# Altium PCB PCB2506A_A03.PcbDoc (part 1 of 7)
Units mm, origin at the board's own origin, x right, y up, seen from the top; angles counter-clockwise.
Board outline 115 x 60 mm, 6 copper layers (Top Layer, Signal Layer 2, Signal Layer 3, Signal Layer 4, Signal Layer 5, Bottom Layer), stack 1.555 mm thick; 376 components, 290 nets, 1297 pads, 901 vias.
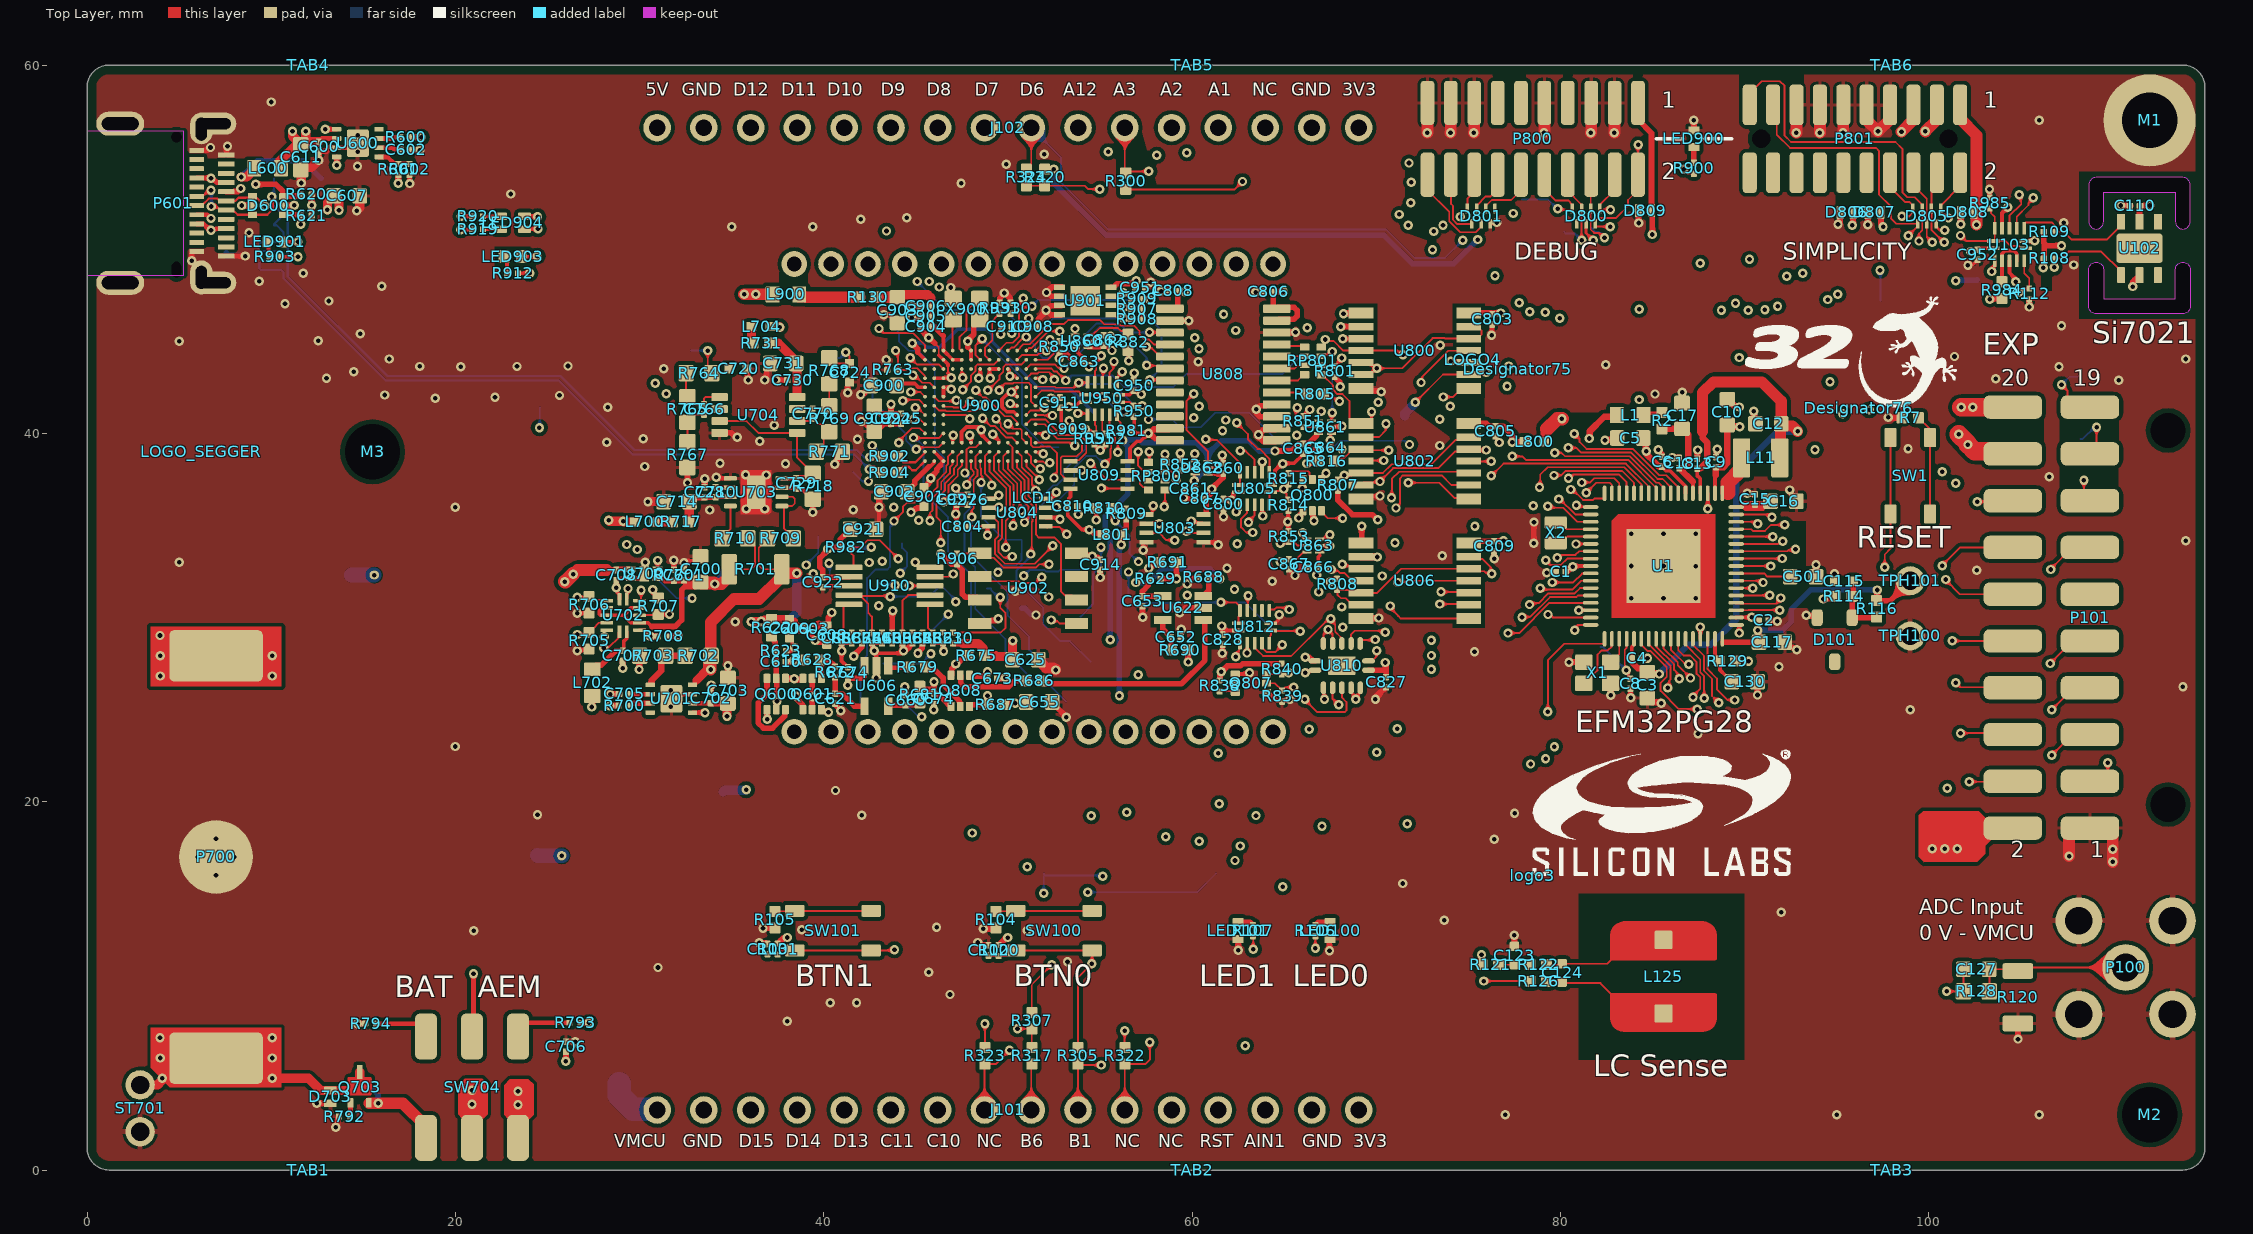
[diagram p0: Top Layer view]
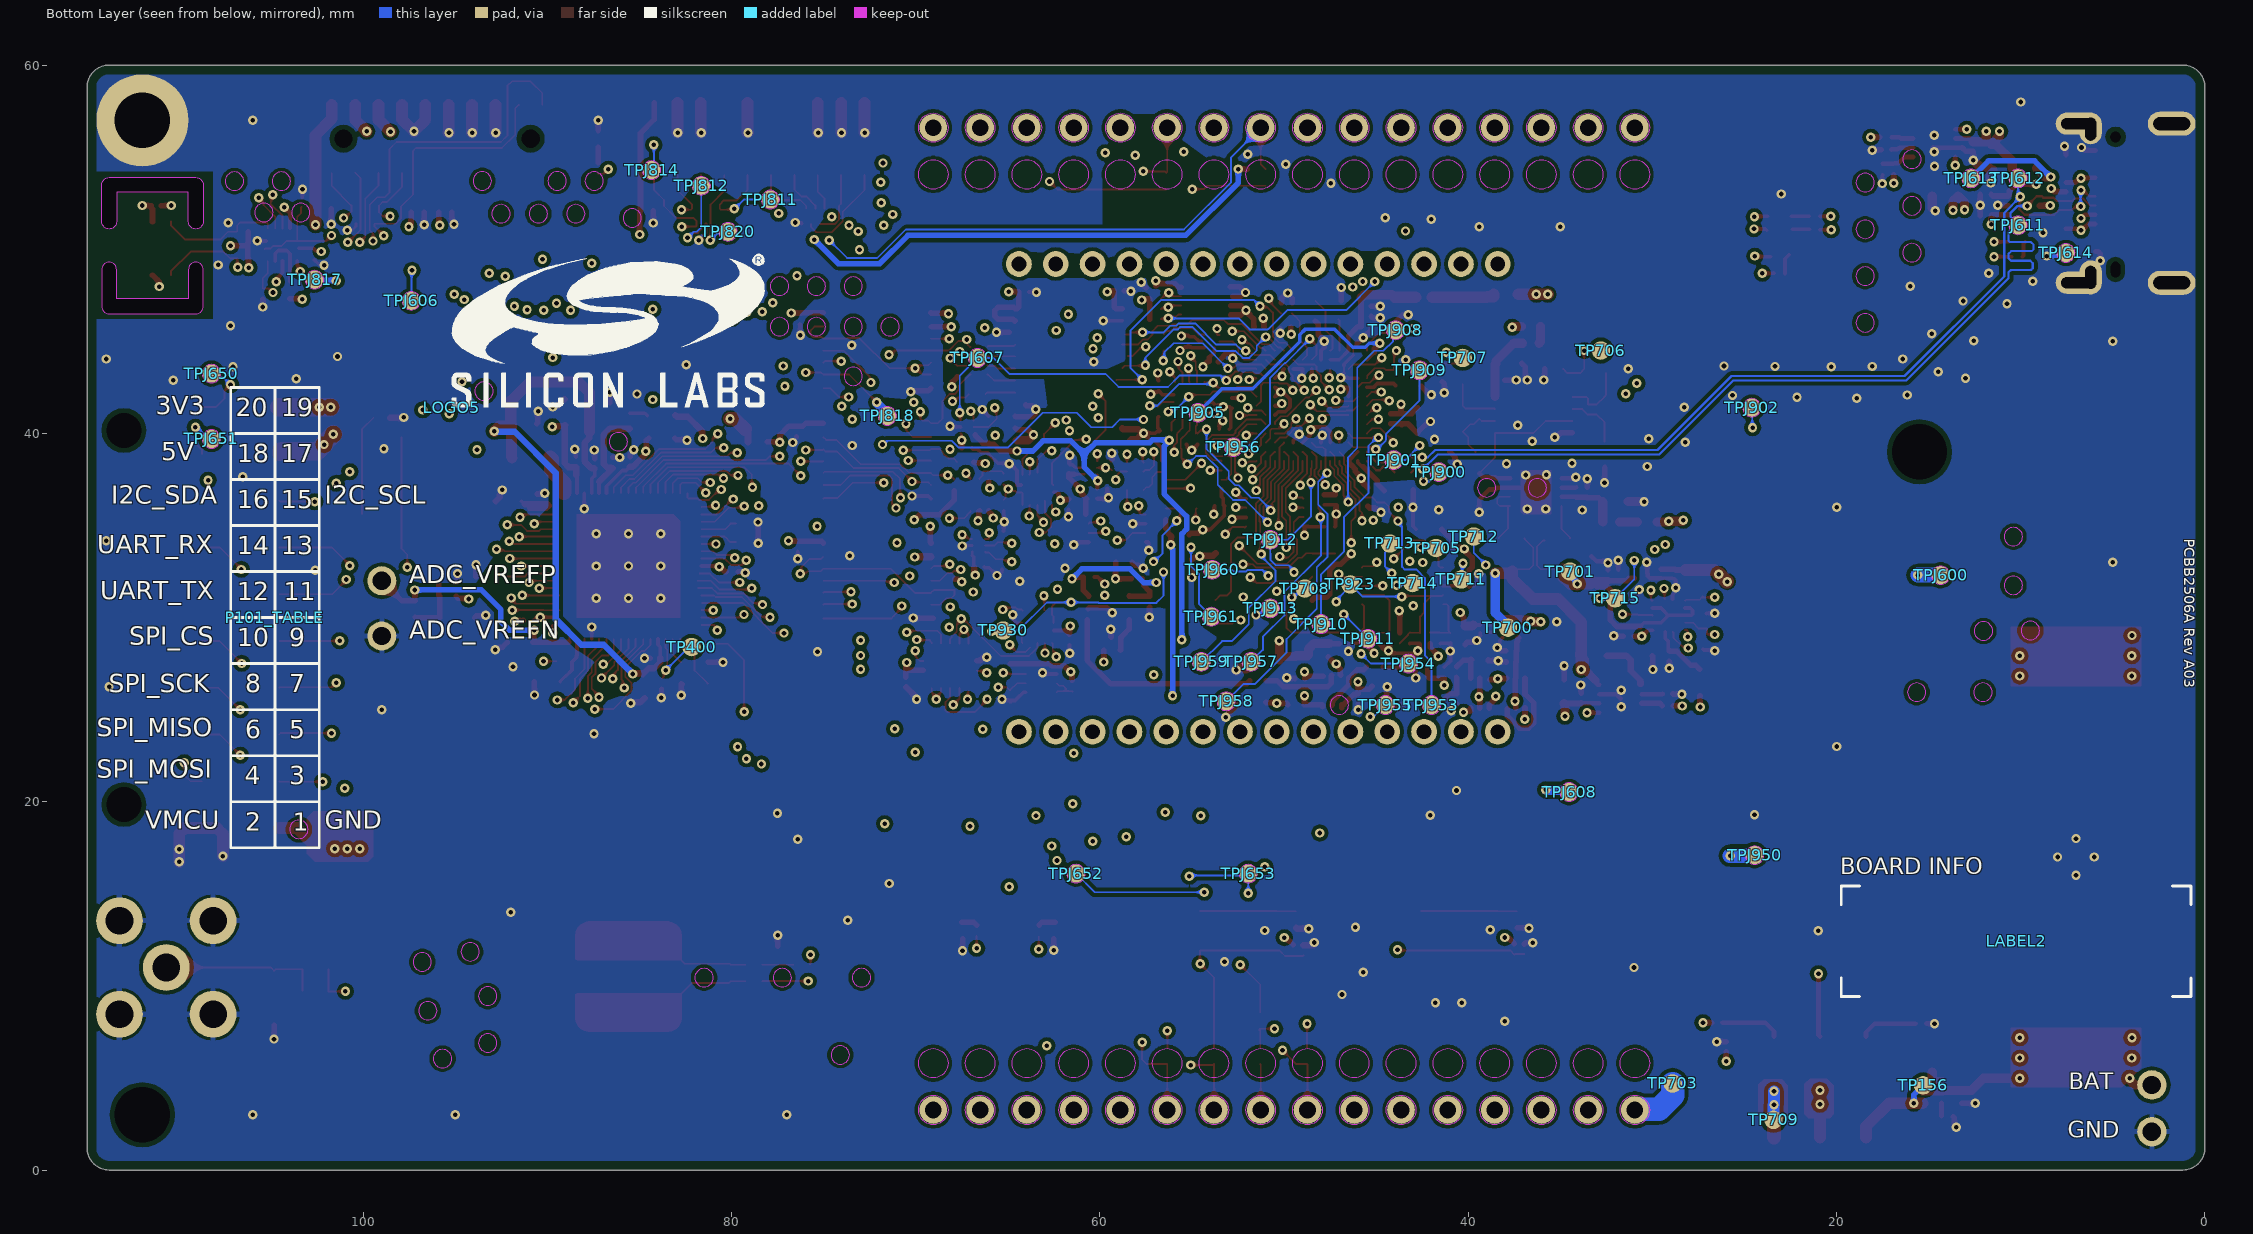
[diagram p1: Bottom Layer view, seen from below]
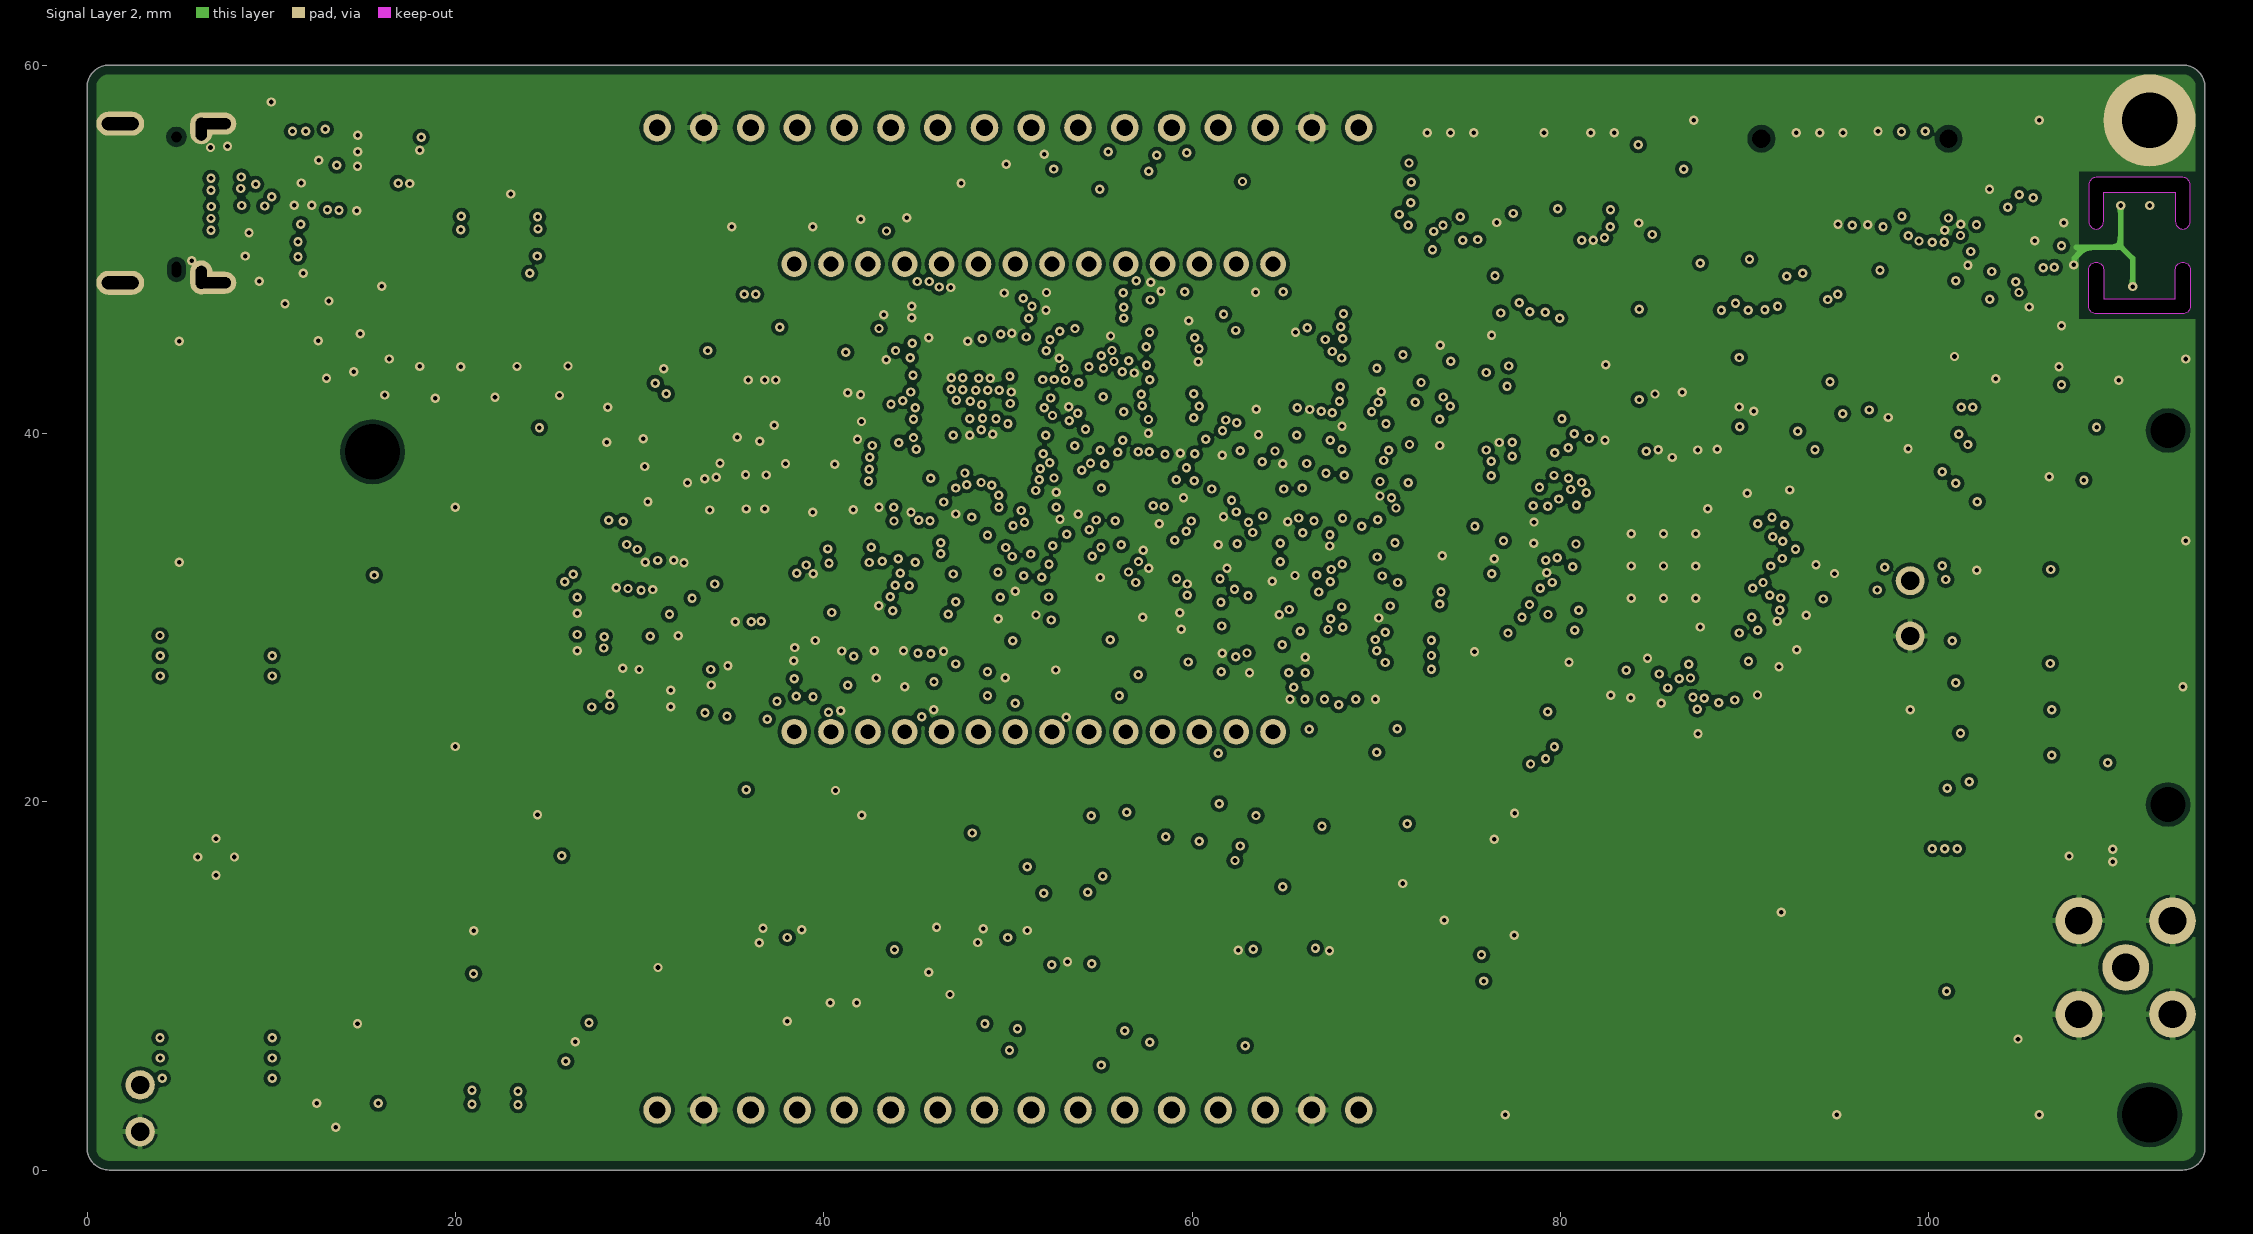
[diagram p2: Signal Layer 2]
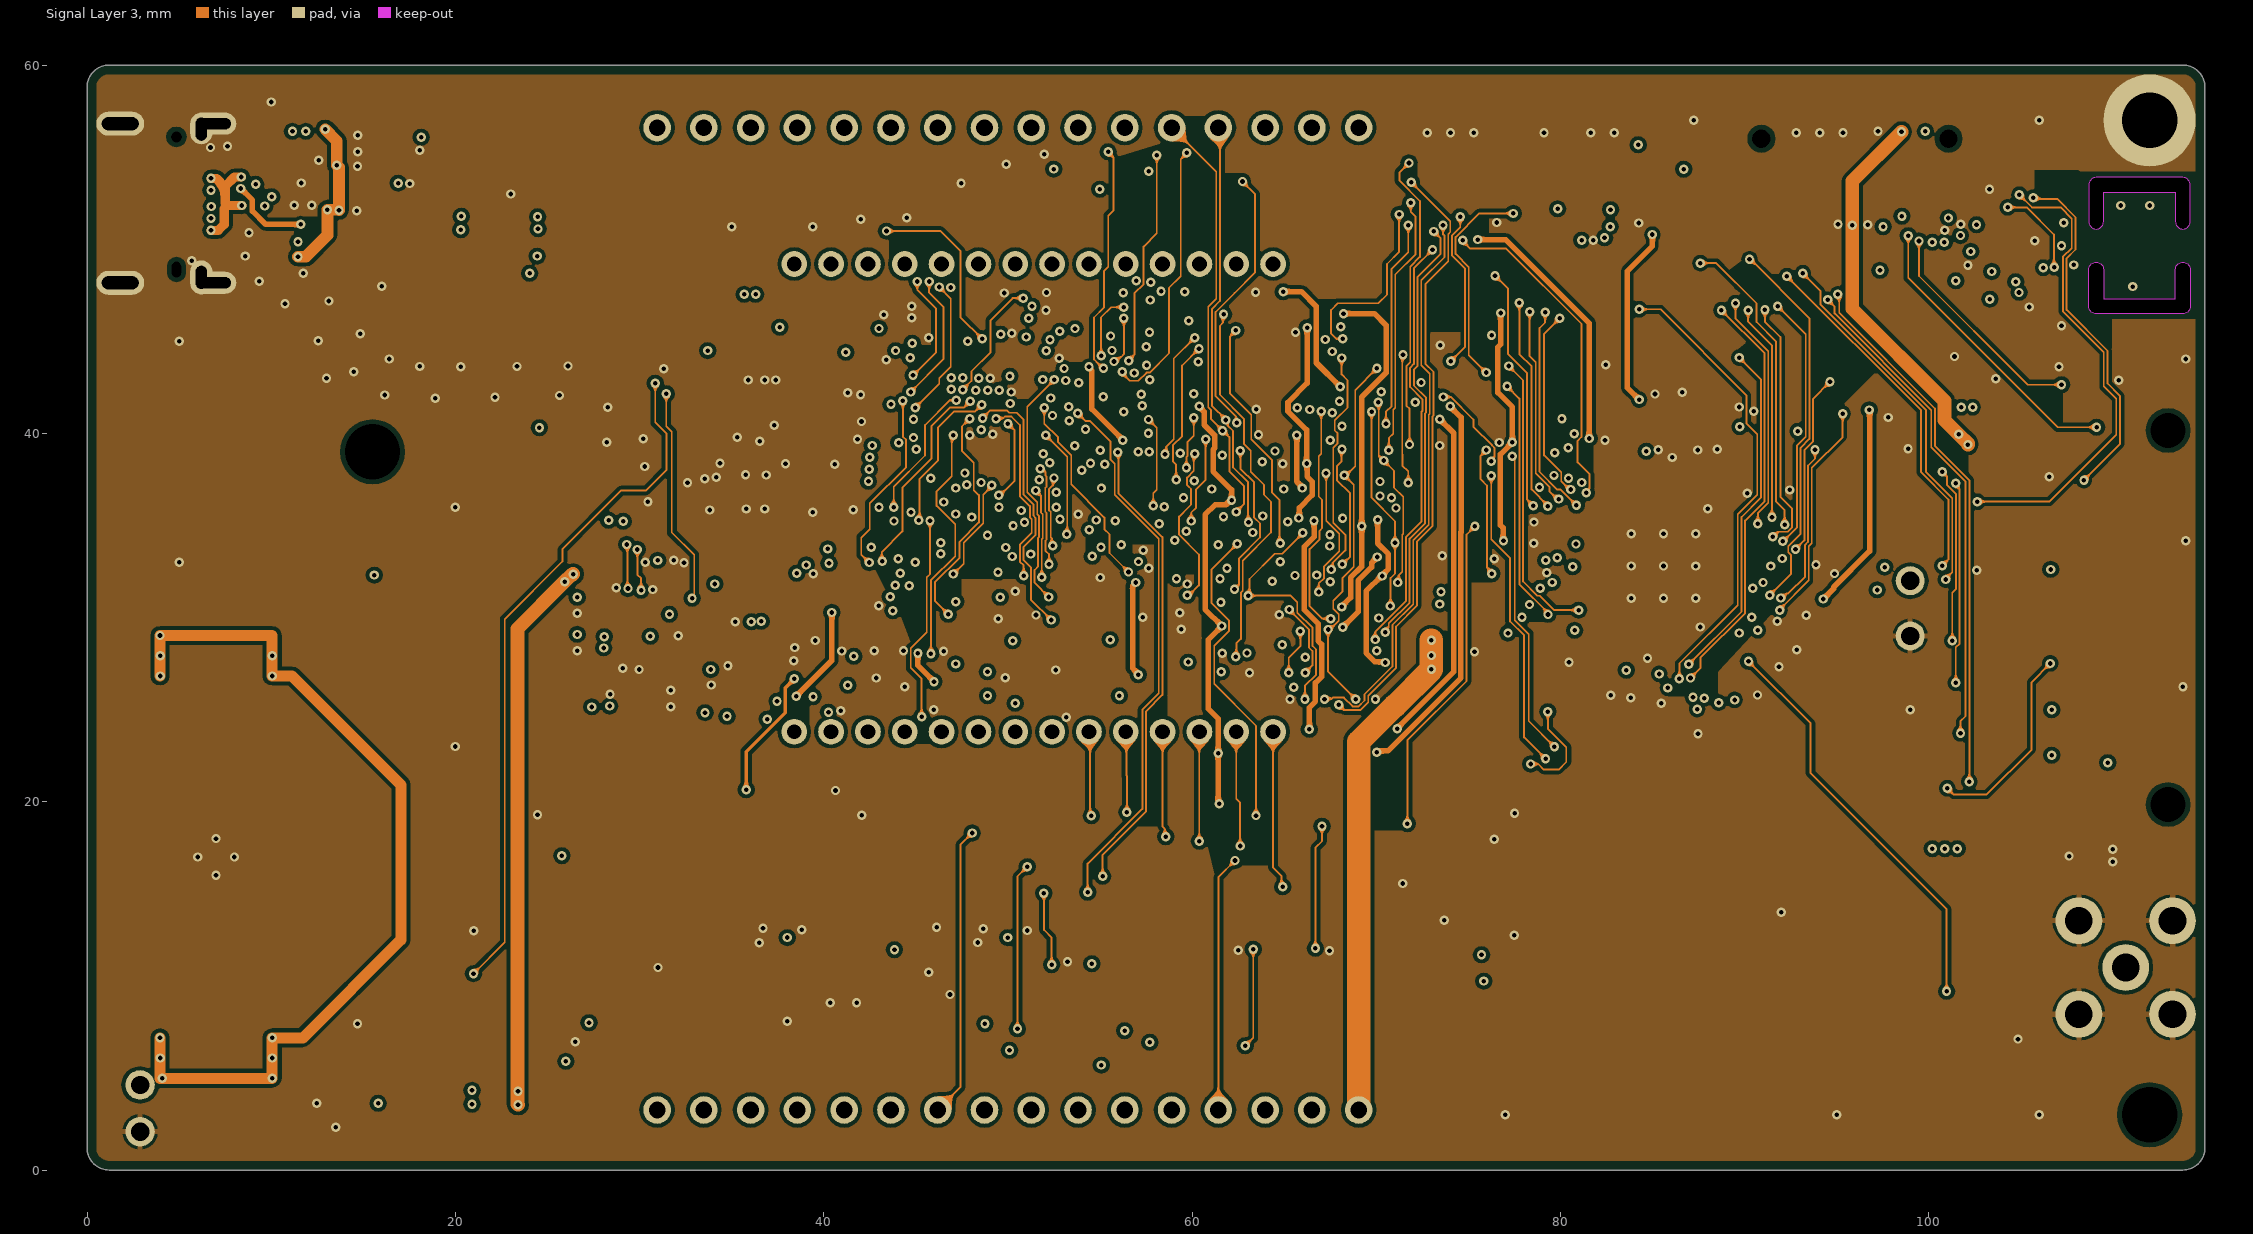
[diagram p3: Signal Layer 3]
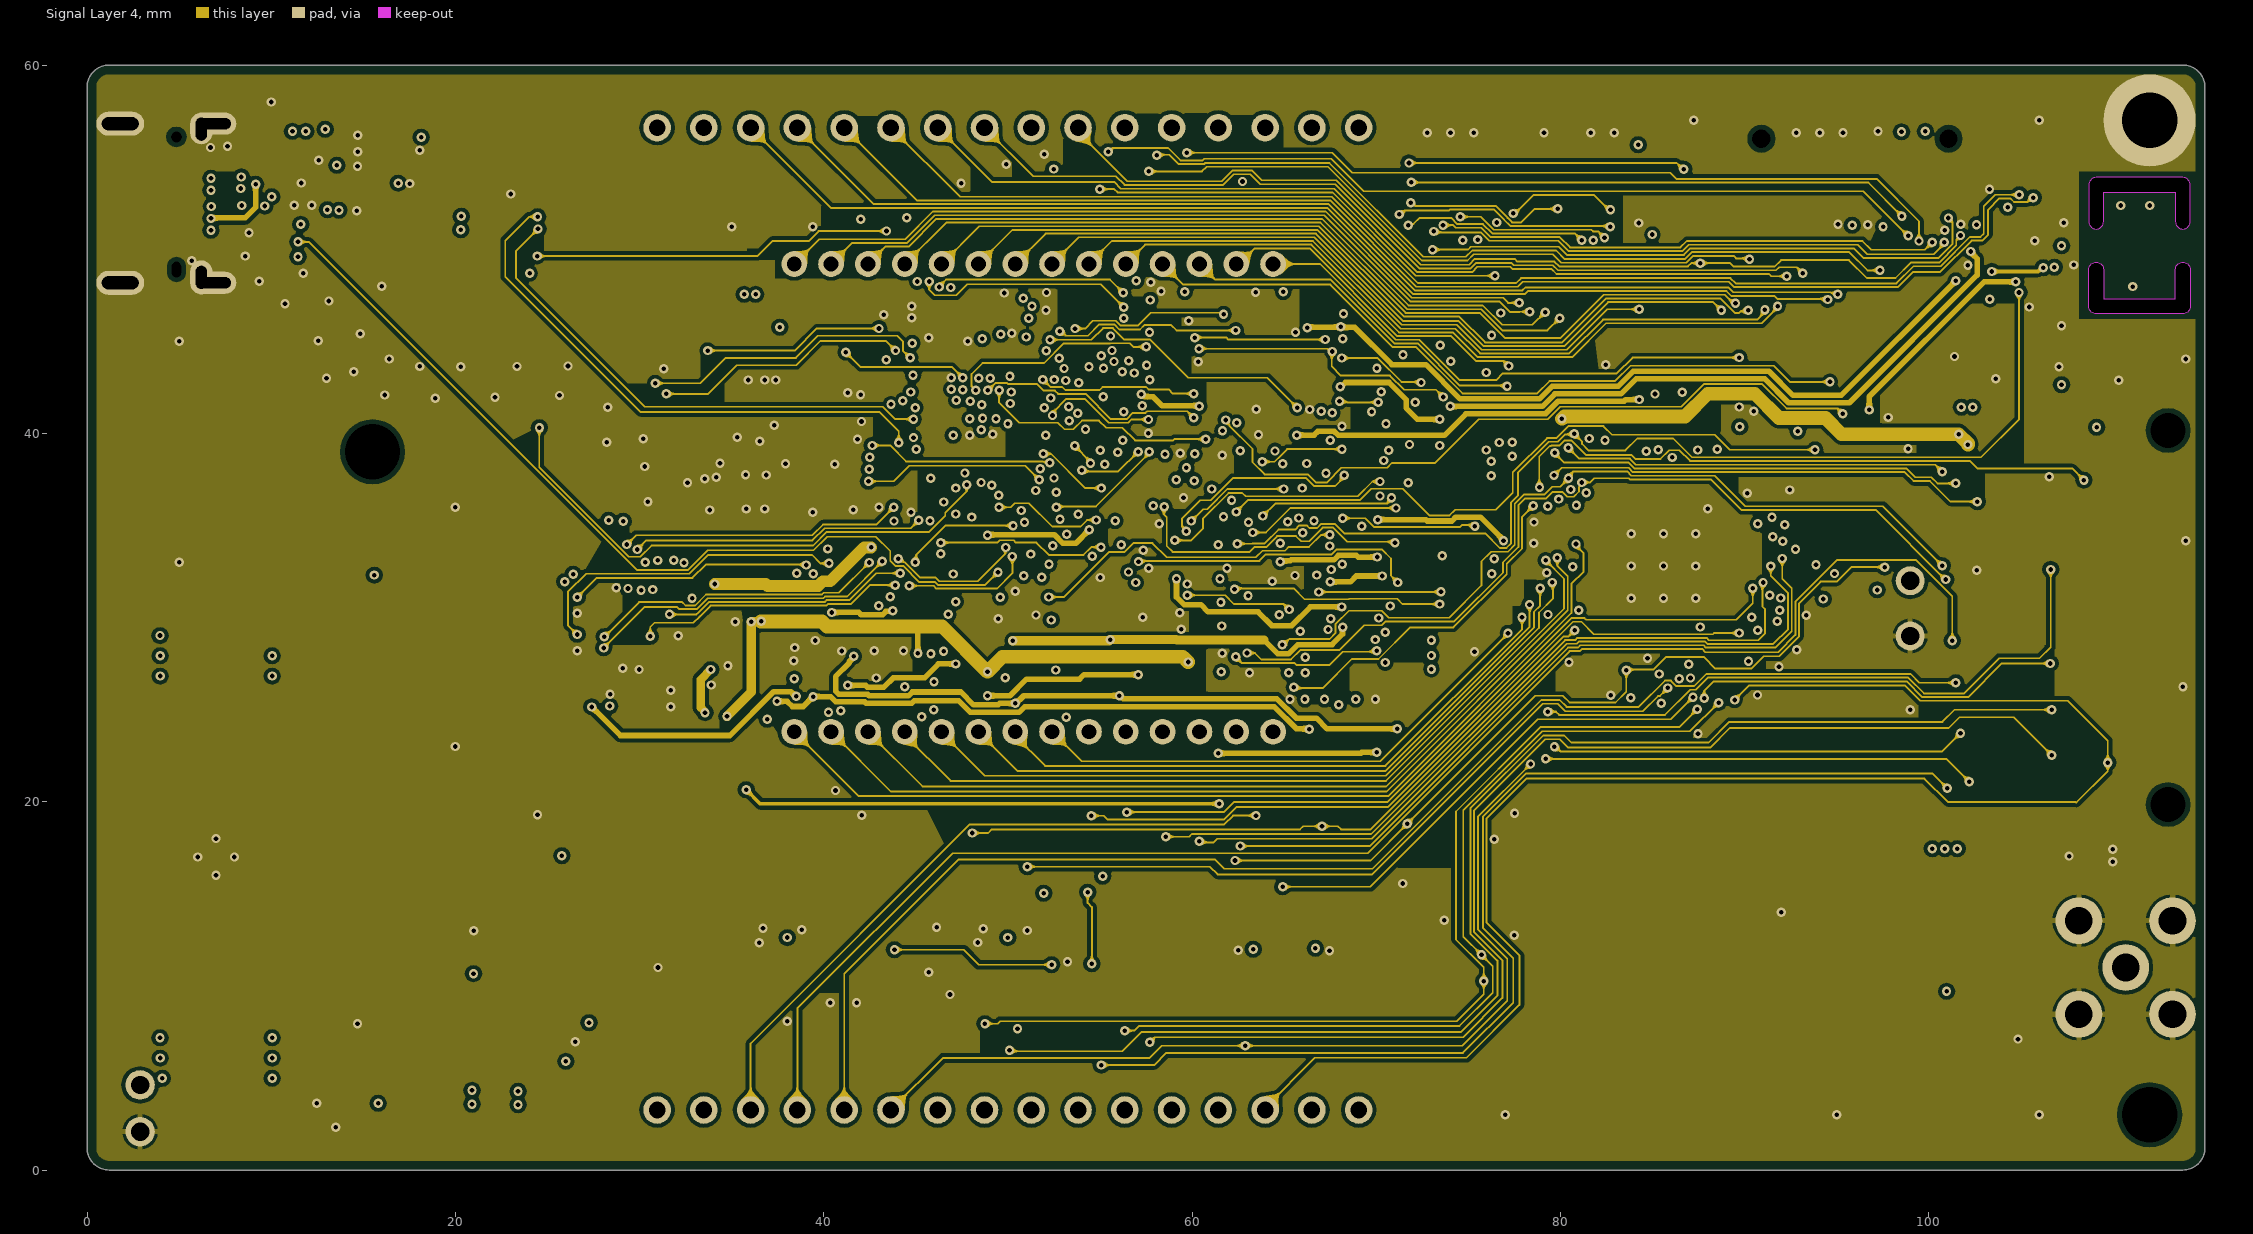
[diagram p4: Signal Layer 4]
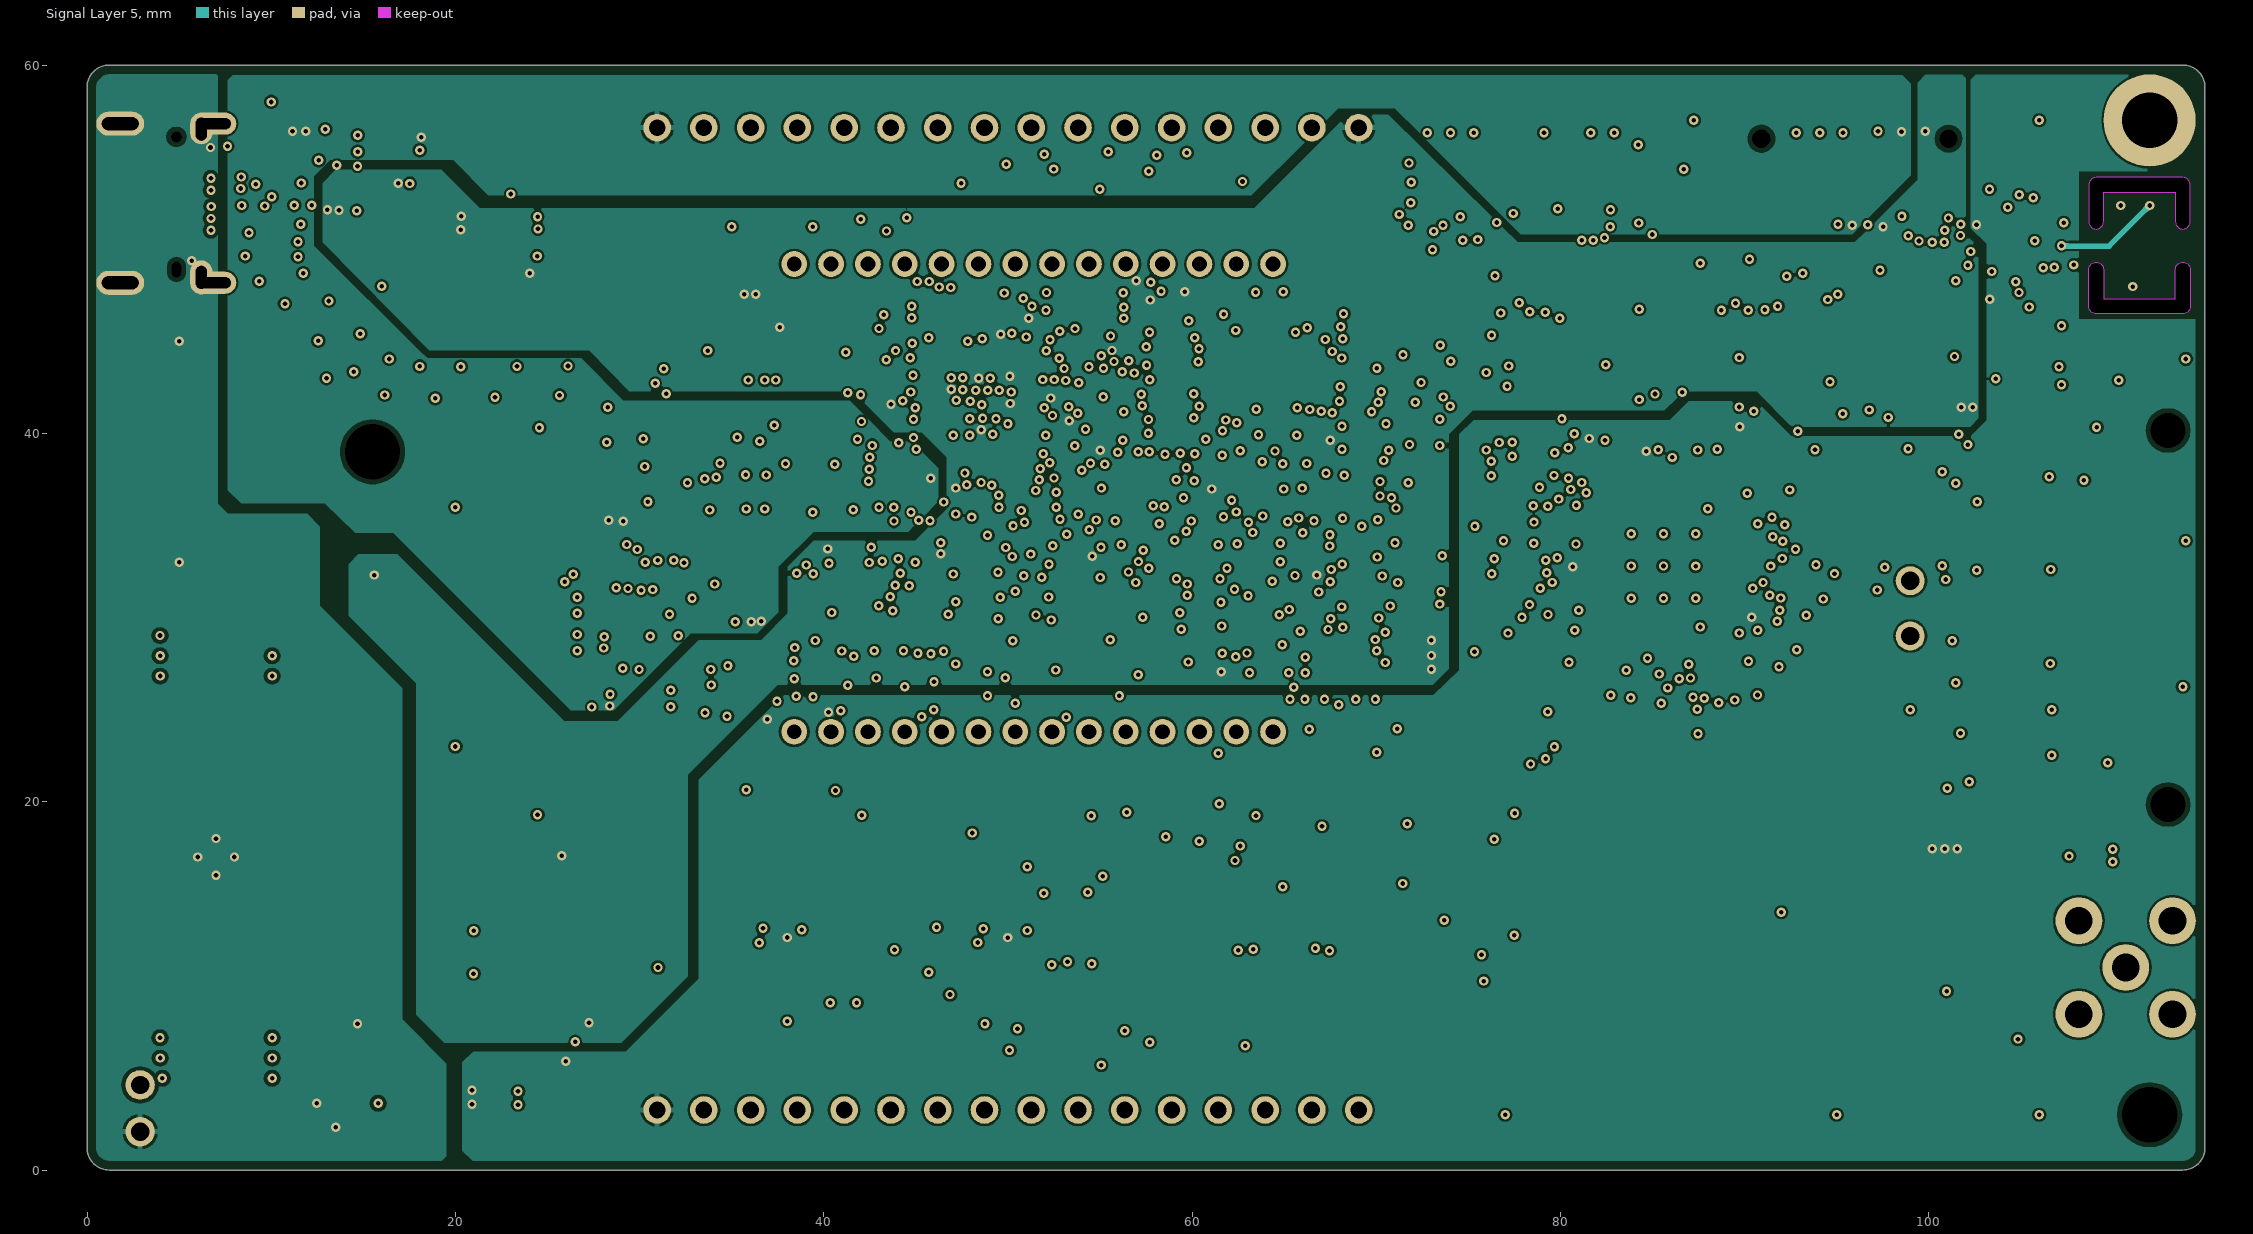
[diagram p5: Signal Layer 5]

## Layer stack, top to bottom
Top Solder: solder mask 0.03, Solder Resist, Dk 3.5
Top Layer: signal copper 0.035
Dielectric 1: prepreg 0.1, FR-4, Dk 4.2
Signal Layer 2: signal copper 0.035
Dielectric 2: core 0.46, Core-009, Dk 4.2
Signal Layer 3: signal copper 0.035
Dielectric 3: prepreg 0.225, PP-006, Dk 4.2
Signal Layer 4: signal copper 0.035
Dielectric 4: core 0.46, Core-009, Dk 4.2
Signal Layer 5: signal copper 0.035
Dielectric  5: prepreg 0.1, FR-4, Dk 4.2
Bottom Layer: signal copper 0.035
Bottom Solder: solder mask 0.03, Solder Resist, Dk 3.5

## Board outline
0,1.2 0,58.8 cw(c1.2,58.8) 1.2,60 113.8,60 cw(c113.8,58.8) 115,58.8 115,1.2 cw(c113.8,1.2) 113.8,0 1.2,0 cw(c1.2,1.2)
cut-out: 108.7,53.5 108.7,51.5 ccw(c109.1,51.5) 109.1,51.1 ccw(c109.1,51.5) 109.5,51.5 109.5,53.1 113.4,53.1 113.4,51.5 ccw(c113.8,51.5) 113.8,51.1 ccw(c113.8,51.5) 114.2,51.5 114.2,53.5 ccw(c113.8,53.5) 113.8,53.9 109.1,53.9 ccw(c109.1,53.5)
cut-out: 108.7,46.9 108.7,48.9 cw(c109.1,48.9) 109.1,49.3 cw(c109.1,48.9) 109.5,48.9 109.5,47.3 113.4,47.3 113.4,48.9 cw(c113.8,48.9) 113.8,49.3 cw(c113.8,48.9) 114.2,48.9 114.2,46.9 cw(c113.8,46.9) 113.8,46.5 109.1,46.5 cw(c109.1,46.9)

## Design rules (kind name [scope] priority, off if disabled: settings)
BoardOutlineClearance BoardOutlineClearance_IGNORE_USB [HasFootprint('FCI_10137065_USB-C_RCPT') and IsKeepOut] p1: gap=0.5 ignorepadtopadclearanceinfootprint=FALSE except(0: Region-OutlineEdge Region-CavityEdge Region-CutoutEdge Region-SplitBarrior Region-SplitContinuation; 0.26: Arc-CutoutEdge Track-CutoutEdge SMDPad-CutoutEdge THPad-CutoutEdge Via-CutoutEdge Fill-CutoutEdge Poly-CutoutEdge Text-CutoutEdge; 0.4: THPad-OutlineEdge)
BoardOutlineClearance [Not HasFootprint('TAB50.5_T1.6_W2.4') or not HasFootprint('FCI_10137065_USB-C_RCPT')] p2: gap=0.5 ignorepadtopadclearanceinfootprint=FALSE except(0.26: Arc-CutoutEdge Track-CutoutEdge SMDPad-CutoutEdge THPad-CutoutEdge Via-CutoutEdge Fill-CutoutEdge Poly-CutoutEdge Region-CutoutEdge Text-CutoutEdge; 0.4: THPad-OutlineEdge)
Clearance Clearance_NPL [(ObjectKind = 'Pad') And (Layer = 'MultiLayer') And (PadIsPlated = 'False')] p1: gap=0.25 ignorepadtopadclearanceinfootprint=FALSE
Clearance Clearance_Polygon_GND [InNet('GND') and InPolygon] p2: gap=0.2 ignorepadtopadclearanceinfootprint=FALSE
Clearance Clearance_Polygon_General [InPolygon] p3: gap=0.125 ignorepadtopadclearanceinfootprint=FALSE
Clearance Clearance_Via_Track [IsVia vs IsTrack] p4: gap=0.089 ignorepadtopadclearanceinfootprint=FALSE except(0: Arc-Hole Track-Hole SMDPad-Hole THPad-Hole Via-Hole Fill-Hole Poly-Hole Region-Hole Text-Hole)
Clearance [All] p5: gap=0.1 ignorepadtopadclearanceinfootprint=FALSE
ComponentClearance ComponentClearance_IGNORE [HasFootprint('TESTJIGG_PCB4002_M14') OR HasFootprint('TAB50.5_T1.6_W2.4') OR HasFootprint('TP_6.0X6.0_MILLOUT_5.0X5.0_TH') Or InComponent('M1')] p1: gap=0 collisioncheckmode=3 verticalgap=0 showdistances=FALSE
ComponentClearance [All] p2: gap=0.2 collisioncheckmode=3 verticalgap=0.254 showdistances=FALSE
DiffPairsRouting DiffPairsRouting_90OHM [InDifferentialPair('USB_90') or InDifferentialPair('USB_90_U900')] p1: maxlimit=0.254 minlimit=0.12 mostfreqgap=0.254 toplayer_maxgap=0.12 toplayer_prefgap=0.12 toplayer_minwidth=0.12 toplayer_maxwidth=0.12 toplayer_prefwidth=0.12 bottomlayer_maxgap=0.12 bottomlayer_prefgap=0.12 bottomlayer_minwidth=0.12 bottomlayer_maxwidth=0.12 bottomlayer_prefwidth=0.12 impedanceprofiledriven=TRUE impedanceprofileid={B4300C99-598D-4438-91CE-854F904B181D} impedanceprofilevalue=90.000000 maxuncoupledlength=50
HoleSize [All] p1: absolutevalues=TRUE maxlimit=10 minlimit=0.1 maxpercent=80.000 minpercent=20.000
HoleToHoleClearance HoleToHoleClearance_general [Not InComponent('P601')] p1: gap=0.254 allowstackedmicrovias=TRUE
MatchedLengths [All] p1: tolerance=0.1 checknetsindiffpair=TRUE checkdiffpairvsdiffpair=FALSE checkxsignals=FALSE checkothers=FALSE
MinimumSolderMaskSliver MinimumSolderMaskSliver_CK_DPDT_JS202011SCQN [All] p1: minsoldermaskwidth=0
MinimumSolderMaskSliver MinimumSolderMaskSliver_WELLSHOW_C02AN31_SMA_TH [HasFootprint('WELLSHOW_C02AN31_SMA_TH')] p2: minsoldermaskwidth=0
MinimumSolderMaskSliver MinimumSolderMaskSliver_DSBGA4_M040_0.8X0.8_TI_YFP [HasFootprint('DSBGA4_M040_0.8X0.8_TI_YFP')] p3: minsoldermaskwidth=0.09
MinimumSolderMaskSliver MinimumSolderMaskSliver_RES_MNR04-8 [HasFootprint('RES_MNR04-8')] p4: minsoldermaskwidth=0.05
MinimumSolderMaskSliver MinimumSolderMaskSliver_TSOP65P640X120-24L [HasFootprint('TSOP65P640X120-24L')] p5: minsoldermaskwidth=0.09
MinimumSolderMaskSliver MinimumSolderMaskSliver_QFN40P800X800X90_HS-69N [HasFootprint('QFN40P800X800X90_HS-69N')] p6: minsoldermaskwidth=0.04
MinimumSolderMaskSliver MinimumSolderMaskSliver_FCI_10137065_USB-C_RCPT [HasFootprint('FCI_10137065_USB-C_RCPT')] p7: minsoldermaskwidth=0
MinimumSolderMaskSliver MinimumSolderMaskSliver_SOT563Diodes [HasFootprint('SOT563_DIODES')] p8: minsoldermaskwidth=0.02
MinimumSolderMaskSliver MinimumSolderMaskSliver_EFM [InComponent('Designator75')] p9: minsoldermaskwidth=0
MinimumSolderMaskSliver MinimumSolderMaskSliver_C0201 [HasFootprint('C0201')] p10: minsoldermaskwidth=0.09
MinimumSolderMaskSliver MinimumSolderMaskSliver_IGNORE [InComponent('LOGO*') vs InComponent('LOGO*')] p11: minsoldermaskwidth=0
MinimumSolderMaskSliver [All] p12: minsoldermaskwidth=0.15
PolygonConnect PolygonConnect_P601 [InComponent('P601')] p1: connectstyle=Direct reliefconductorwidth=0.254 reliefentries=4 polygonreliefangle="90 Angle" airgapwidth=0.254
PolygonConnect [InComponent('J101') or InComponent('J102') vs InNet('GND') and not OnLayer('Signal Layer 2')] p2: connectstyle=NoConnect reliefconductorwidth=0.254 reliefentries=4 polygonreliefangle="90 Angle" airgapwidth=0.2
PolygonConnect PolygonConnect_Direct_Connect [InComponent('M1') or InComponent('J1') or InComponent('P700')] p3: connectstyle=Direct reliefconductorwidth=0.33 reliefentries=4 polygonreliefangle="90 Angle" airgapwidth=0.152
PolygonConnect PolygonConnect_general [All] p4: thpad.connectstyle=Relief thpad.reliefconductorwidth=0.3 thpad.reliefentries=4 thpad.polygonreliefangle="90 Angle" thpad.airgapwidth=0.15 smdpad.connectstyle=Relief smdpad.reliefconductorwidth=0.2 smdpad.reliefentries=4 smdpad.polygonreliefangle="90 Angle" smdpad.airgapwidth=0.15 via.connectstyle=Direct via.reliefconductorwidth=0.33 via.reliefentries=4 via.polygonreliefangle="90 Angle" via.airgapwidth=0.127
RoutingVias RoutingVias_Through [InDrillLayerPair('Top Layer - Bottom Layer')] p1: holewidth=0.25 width=0.508 viastyle="Through Hole" minholewidth=0.25 minwidth=0.508 maxholewidth=1 maxwidth=1.5 useviatemplates=TRUE viatemplateguid#1={5509B7CA-6DD0-459B-8D94-B04A75BB8EC3} viatemplatename#1=v51h25m0mx0(Tol8-8)
ShortCircuit ShortCircuit_General [All] p1: allowed=FALSE
SilkToSilkClearance [All] p1: silktosilkclearance=0.102
SilkToSolderMaskClearance [IsPad] p1: minsilkscreentomaskgap=0.102 clearancetoexposedcopper=TRUE
SolderMaskExpansion [All] p1: expansion=0.05 istentingtop=FALSE
UnRoutedNet [All] p1: checkbadconnections=TRUE
Width [All] p1: maxlimit=5.08 minlimit=0.1 preferedwidth=0.1 minimp=50.000000 maximp=50.000000 favimp=50.000000
21 further rules are at their usual default settings.

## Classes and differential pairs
net class USB_90: N16942491 N16942503 USB_DM USB_DP
differential pair USB_90_U900: +N16942503 -N16942491
differential pair USB_90: +USB_DP -USB_DM
differential pair ETH_RX: +"" -""
differential pair ETH_TX: +"" -""
differential pair USB: +"" -""

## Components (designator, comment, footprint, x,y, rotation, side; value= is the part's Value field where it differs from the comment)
C1 "100N" C0201#1 80.015,32.49 r180 top
C2 "100N" C0201#1 91.04,29.844 r0 top
C3 "4U7" C0603 84.725,26.329 r270 top
C4 "10N" C0201#2 84.147,27.804 r0 top
C5 "4U7" C0603 83.797,39.75 r180 top
C6 "100N" C0201#2 85.526,38.46 r90 top
C8 "100N" C0201#2 83.8,26.413 r270 top
C9 "100N" C0201#2 88.452,38.445 r90 top
C10 "10U" C0603 89.067,41.156 r90 top
C12 "4U7" C0603 91.295,40.525 r180 top
C13 "100N" C0201#2 87.433,38.354 r90 top
C15 "100N" C0201#2 90.567,36.418 r90 top
C16 "1U" C0603 92.118,36.316 r0 top
C17 "4U7" C0603 86.608,40.955 r90 top
C18 "10N" C0201#2 86.455,38.389 r90 top
C102 "1N" C0201#2 48.95,11.924 r90 top
C103 "1N" C0201#2 36.95,12 r90 top
C110 "100N" C0201#2 111.2,52.35 r180 top
C115 "1U" C0402 95.4,31.975 r180 top
C117 "10U" C0603 91.491,28.668 r0 top
C123 "100N" C0402 77.5,11.65 r90 top
C124 "330P" C0402 80.1,10.7 r270 top
C127 "4U7" C0603 102.589,10.9 r180 top
C130 "10N" C0603 90.009,26.515 r0 top
C501 "4U7" C0603 93.183,32.226 r180 top
C600 "100N" C0201#2 12.576,55.559 r270 top
C602 "33N" C0201#2 17.3,55.411 r0 top
C607 "10U" C0603 14.1,52.9 r0 top
C608 "1U" C0402 40.169,29.05 r270 top
C609 "1U" C0402 38.144,29.4 r270 top
C610 "1N" C0201#2 37.669,27.6 r0 top
C611 "10U" C0603 11.6,55 r270 top
C621 "100N" C0201#2 40.619,25.59 r270 top
C625 "10U" C0603 50.956,27.712 r0 top
C632 "10N" C0201#2 45.919,28.89 r270 top
C635 "10N" C0201#2 44.269,28.89 r270 top
C638 "10N" C0201#2 40.969,28.89 r270 top
C641 "10N" C0201#2 42.619,28.89 r270 top
C652 "100N" C0201#2 59.122,28.945 r0 top
C653 "100N" C0201#2 57.3,30.886 r270 top
C655 "10U" C0603 51.695,25.415 r0 top
C660 "100N" C0201#2 44.44,25.509 r90 top
C673 "100N" C0201#2 49.138,26.687 r0 top
C674 "100N" C0201#2 45.98,25.593 r270 top
C700 "10U" C0603 33.311,32.631 r90 top
C701 "100N" C0201#2 32.411,32.3 r90 top
C702 "100N" C0201#2 33.858,25.629 r90 top
C703 "10U" C0603 34.798,26.035 r90 top
C705 "33N" C0201#2 29.159,25.857 r180 top
C706 "100N" C0201#2 26,6.7 r90 top
C707 "100N" C0201#2 29.083,27.915 r270 top
C708 "100N" C0201#2 28.733,32.308 r270 top
C710 "100N" C0201#2 34.129,36.808 r90 top
C714 "10U" C0603 32.011,36.296 r180 top
C720 "1N" C0402 35.35,43.5 r0 top
C724 "1N" C0402 41.4,43.3 r270 top
C728 "100N" C0201#2 33.529,36.808 r90 top
C729 "2N2" C0201#2 38.504,37.283 r270 top
C730 "100N" C0201#2 38.3,42.9 r180 top
C731 "10U" C0603 37.8,43.8 r180 top
C766 "10P" C0201#2 33.5,41.3 r90 top
C770 "10P" C0201#2 39.4,41.075 r90 top
C800 "100N" C0201#2 61.707,36.161 r270 top
C803 "100N" C0201#2 76.301,46.191 r270 top
C804 "100N" C0201#2 47.516,34.936 r180 top
C805 "100N" C0201#2 76.479,40.116 r270 top
C806 "100N" C0201#2 64.147,47.703 r180 top
C807 "100N" C0201#2 60.42,36.445 r180 top
C808 "100N" C0201#2 58.95,47.75 r180 top
C809 "100N" C0201#2 76.402,33.863 r270 top
C810 "100N" C0201#2 53.5,36.055 r0 top
C827 "100N" C0201#2 70.535,26.493 r270 top
C828 "100N" C0201#2 61.67,28.805 r270 top
C860 "100N" C0201#2 61.695,38.1 r90 top
C861 "100N" C0201#2 59.884,36.994 r180 top
C862 "100N" C0201#2 55.2,45.05 r90 top
C863 "100N" C0201#2 53.85,43.9 r180 top
C864 "100N" C0201#2 67.225,39.214 r180 top
C865 "100N" C0201#2 66.036,39.17 r270 top
C866 "100N" C0201#2 66.582,32.745 r180 top
C867 "100N" C0201#2 65.256,32.89 r270 top
C900 "1U" C0603 43.25,42.6 r180 top
C901 "1U" C0402 45.45,36.55 r270 top
C902 "4U7" C0603 43.825,36.825 r180 top
C903 "10U" C0603 44,46.7 r270 top
C904 "10N" C0201#2 45.55,45.8 r180 top
C905 "10N" C0201#2 45.55,46.35 r180 top
C906 "10N" C0201#2 45.55,46.9 r180 top
C907 "4U7" C0603 42.75,40.8 r270 top
C908 "100N" C0201#2 51.35,45.8 r0 top
C909 "100N" C0201#2 53.25,40.225 r180 top
C910 "100N" C0201#2 49.95,45.8 r0 top
C911 "100N" C0201#2 52.825,41.675 r270 top
C914 "100N" C0201#2 55.013,32.864 r270 top
C921 "4U7" C0603 42.134,34.792 r0 top
C922 "100N" C0201#2 39.946,31.92 r270 top
C924 "100N" C0201#2 43.65,40.8 r270 top
C925 "100N" C0201#2 44.2,40.8 r270 top
C926 "100N" C0201#2 47.808,36.4 r270 top
C927 "100N" C0201#2 47.225,36.4 r270 top
C950 "10N" C0201#2 56.825,42.6 r90 top
C951 "100N" C0201#2 57.201,47.904 r0 top
C952 "100N" C0201#2 102.648,49.698 r270 top
D101 "ADR1581" SOT23 94.9,28.8 r270 top
D600 "DT1446-04" SOT563_DIODES 9.825,52.375 r180 top
D703 "ESD" X2-DFN1006-2 13.2,3.975 r270 top
D800 "PUSB3AB6_0" DFN2111-7_M050_1.2X2.1_NXP 81.4,51.8 r270 top
D801 "PUSB3AB6_0" DFN2111-7_M050_1.2X2.1_NXP 75.7,51.8 r270 top
D805 "PUSB3AB6_0" DFN2111-7_M050_1.2X2.1_NXP 99.9,51.8 r270 top
D806 "ESD" X2-DFN1006-2 95.55,52 r180 top
D807 "ESD" X2-DFN1006-2 97.05,52 r180 top
D808 "ESD" X2-DFN1006-2 102.1,52 r180 top
D809 "ESD" X2-DFN1006-2 84.6,52.1 r180 top
Designator75 "Comment" LOGO_EFM32_W18.0 77.7,43.5 r0 top
Designator76 "Comment" LOGO_GECKO_H6.0 96.2,41.4 r0 top
J101 "1X16 2.54MM" HDR_M254-1X16_NO_3D 30.95,3.262 r0 top locked
J102 "1X16 2.54MM" HDR_M254-1X16_NO_3D 30.95,56.602 r0 top locked
L1 "74279266" COIL_0603_L 83.797,40.998 r0 top
L11 "2U2" COIL_1008 90.882,38.673 r0 top
L125 "470uH" COIL_BOURNS_SDR0604 85.6,10.5 r270 top
L600 "742792662" COIL_0603_L 9.8,54.4 r0 top
L700 "742792796" COIL_0402 30.283,35.195 r0 top
L702 "74279266" COIL_0603_L 27.432,26.467 r90 top
L704 "742792796" COIL_0402 36.6,45.8 r180 top
L800 "742792796" COIL_0402 78.591,39.551 r180 top
L801 "742792796" COIL_0402 55.675,34.5 r180 top
L900 "74279266" COIL_0603_L 37.95,47.55 r0 top
LABEL2 "Comment" LABEL_4CORNERS_19.0X6.0 10.25,12.425 r180 bottom
LCD1 "CL010-1087-04" LCD_TRI-T_CL010-1087-03 51.4,36.5 r0 top locked
LED100 "Yellow" LED_0402_CAT2 67.5,13 r270 top
LED101 "Yellow" LED_0402_CAT2 62.5,13 r270 top
LED900 "YELLOW" LED_0402_CAT2 87.25,56 r90 top
LED901 "BLUE" LED_0402_CAT2 10.2,50.4 r0 top
LED903 "RED" DIOC1005X04N 23.101,49.6 r180 top
LED904 "LED_G_R" LED_AVAGO_HSMF-C165-4 23.101,51.439 r0 top
logo3 "Comment" LOGO_SILABS_W14.0_SILK 78.5,16 r0 top locked
LOGO4 "Comment" LOGO_EFM32_W18.0 75.232,44 r0 top locked
LOGO5 "Comment" LOGO_SILABS_W18.0 95.2,41.4 r180 bottom locked
LOGO_SEGGER "Comment" LOGO_SEGGER_10.0X5.0_SM 6.2,39 r0 top locked
M1 "HOLE_PTH_3MM" HOLE_3.0_5.0_PL 112,57 r0 top locked
M2 "Comment" HOLE_3.0_NPL 112,3 r0 top locked
M3 "Comment" HOLE_3.0_NPL 15.5,39 r90 top locked
P100 "SMA" WELLSHOW_C02AN31_SMA_TH 110.7,11 r0 top
P101 "HEADER_2X10_2.54MM_TH" WCON_1125B-1210_HOR_PEG-2X10 113,19.84 r90 top locked
P101_TABLE "Comment" LABEL_P101_PIN_TABLE_SL 104.8,30 r180 bottom
P601 "AMPHENOL_USB_TYPE-C" FCI_10137065_USB-C_RCPT 4.85,52.5 r270 top
P700 "CR2032" BAT_HOLD_MPD_BK-912_CR2032 7,17 r270 top locked
P800 "HEADER_DEBUG_ETM" WCON_3132_HDR_M127_SMD-2X10 78.5,56 r180 top locked
P801 "HEADER_2X10_1.27MM_SMD" HDR_SULLINS_M127_PEG-2X10 101.08,56 r180 top locked
Q600 "BSS84" SOT563_DIODES 37.419,25.85 r90 top
Q601 "DMN5L06VK" SOT563_DIODES 39.369,25.85 r90 top
Q703 "DMG3415" X2-DFN2015-3_DIODES 14.8,4.55 r90 top
Q800 "DMN5L06VK" SOT563_DIODES 66.533,36.65 r270 top
Q807 "DMN5L06VK" SOT563_DIODES 63.2,26.438 r180 top
Q808 "BSS84" SOT563_DIODES 47.415,26.019 r90 top
R2 "1R" R0402 85.522,40.698 r270 top
R7 "100R" R0402 99,40.85 r0 top
R100 "1M" R0201 49.5,11.924 r90 top
R101 "1M" R0201 37.5,12 r90 top
R104 "100R" R0402 49.35,13.6 r270 top
R105 "100R" R0402 37.35,13.6 r270 top
R106 "2K05" R0201 66.7,13 r270 top
R107 "2K05" R0201 63.3,13 r270 top
R108 "4K7" R0201 106.55,49.5 r0 top
R109 "4K7" R0201 106.55,50.95 r0 top
R112 "10M" R0201 105.461,47.574 r270 top
R114 "16K2" R0402 95.4,31.15 r180 top
R116 "205R" R0402 97.175,30.475 r270 top
R120 "49R9" R1206 104.845,9.382 r90 top
R121 "100R" R0402 76.2,11.15 r0 top
R122 "0R" R0402 78.8,11.15 r0 top
R126 "1K5" R0402 78.8,10.25 r0 top
R128 "549R" R0603 102.589,9.7 r180 top
R129 "14R" R0402 89.073,27.638 r180 top
R130 "1R" R0402 42.4,47.4 r0 top
R300 "0R" R0402 56.4,53.7 r270 top
R305 "0R" R0402 53.8,6.2 r90 top
R307 "0R" R0402 51.3,8.1 r90 top
R317 "0R" R0402 51.3,6.2 r270 top
R320 "10K" R0402 52,53.9 r90 top
R322 "0R" R0402 56.35,6.2 r270 top
R323 "0R" R0402 48.75,6.2 r270 top
R324 "1K" R0402 51,53.9 r270 top
R600 "10K" R0201 17.3,56.087 r0 top
R601 "180K" R0201 16.9,54.335 r270 top
R602 "110K" R0201 17.5,54.335 r90 top
R620 "5K1" R0201 11.9,52.975 r180 top
R621 "5K1" R0201 11.9,51.825 r180 top
R622 "47R" R0402 37.169,29.45 r90 top
R623 "10K" R0201 37.669,28.2 r180 top
R628 "1M" R0402 39.369,27.7 r180 top
R629 "1K" R0201 58,32.1 r0 top
R630 "4K7" R0201 47.019,28.89 r270 top
R631 "10K" R0201 46.469,28.89 r90 top
R633 "47K" R0201 45.369,28.89 r270 top
R634 "47K" R0201 44.819,28.89 r90 top
R636 "47K" R0201 42.069,28.89 r270 top
R637 "47K" R0201 41.519,28.89 r90 top
R639 "47K" R0201 43.719,28.89 r90 top
R640 "47K" R0201 43.169,28.89 r90 top
R672 "1K" R0201 40.619,27.04 r90 top
R674 "4K7" R0201 41.313,27 r90 top
R675 "3R3" R0402 48.278,27.931 r0 top
R679 "0R" R0402 45.079,27.315 r0 top
R681 "33R" R0402 45.216,25.82 r90 top
R686 "0R" R0402 51.418,26.559 r180 top
R687 "3R3" R0402 49.346,25.275 r0 top
R688 "4K7" R0201 60.604,32.2 r180 top
R690 "33R" R0402 59.335,28.228 r0 top
R691 "1M" R0402 58.692,33 r180 top
R700 "10K" R0201 29.159,25.222 r180 top
R701 "4R7" R1206 36.289,32.624 r180 top
R702 "180K" R0603 33.175,27.924 r0 top
R703 "110K" R0603 30.706,27.924 r0 top
R705 "267R" R0402 27.255,28.739 r90 top
R706 "10K2" R0402 27.255,30.7 r90 top
R707 "24K9" R0402 31.014,30.621 r270 top
R708 "1M" R0201 31.293,28.981 r180 top
R709 "1K8" R0603 37.643,34.3 r180 top
R710 "1K8" R0603 35.178,34.3 r0 top
R717 "10R" R0402 32.234,35.195 r0 top
R718 "12K" R0603 39.404,37.133 r90 top
R731 "1R" R0402 36.6,44.9 r180 top
R760 "330K" R0201 31.861,32.3 r270 top
R763 "100K" R0201 43.75,43.45 r0 top
R764 "90R9" R0603 33.225,43.275 r0 top
R765 "51K" R0603 32.6,41.3 r90 top
R767 "160R" R0603 32.6,38.85 r90 top
R768 "90R9" R0603 40.3,43.4 r90 top
R769 "51K" R0603 40.3,40.8 r90 top
R771 "51K" R0603 40.3,39 r180 top
R792 "1K" R0201 13.975,2.9 r0 top
R793 "10K" R0201 26.5,8 r0 top
R794 "510K" R0201 15.4,7.95 r180 top
R801 "47K" R0201 67.752,43.367 r270 top
R805 "33R" R0402 66.676,42.139 r0 top
R807 "4K7" R0201 67.92,37.194 r90 top
R808 "4K7" R0201 67.876,31.806 r270 top
R809 "100K" R0201 56.425,35.625 r270 top
R810 "33R" R0402 55.2,35.925 r0 top
R814 "100K" R0201 65.232,36.1 r90 top
R815 "1K" R0201 65.232,37.532 r270 top
R816 "100K" R0402 67.298,38.5 r180 top
R838 "100K" R0201 61.5,26.287 r90 top
R839 "10M" R0201 64.888,25.736 r90 top
R840 "100K" R0201 64.87,27.205 r90 top
R850 "100K" R0201 52.8,44.7 r90 top
R851 "100K" R0201 66.048,40.649 r270 top
R852 "100K" R0201 59.354,38.297 r270 top
R853 "100K" R0201 65.24,34.398 r270 top
R882 "220R" R0402 56.525,44.95 r270 top
R900 "2K05" R0201 87.25,54.4 r90 top
R902 "33R" R0402 43.55,38.75 r0 top
R903 "5K76" R0201 10.2,49.6 r180 top
R904 "33R" R0402 43.55,37.875 r0 top
R906 "10K" R0201 47.244,33.182 r270 top
R907 "4K7" R0201 57,46.75 r180 top
R908 "4K7" R0201 57,46.2 r180 top
R909 "10K" R0201 57,47.3 r180 top
R912 "2K37" R0201 23.101,48.7 r180 top
R919 "1K" R0201 21.201,51.089 r0 top
R920 "2K37" R0201 21.201,51.789 r0 top
R930 "1K" R0201 50.15,46.8 r90 top
R931 "1K" R0201 49.55,46.8 r90 top
R950 "100K" R0201 56.825,41.2 r270 top
R951 "100K" R0201 54.7,39.7 r90 top
R952 "100K" R0201 55.3,39.7 r90 top
R981 "100K" R0201 56.421,40.149 r0 top
R982 "10K" R0201 41.206,33.821 r0 top
R984 "0R" R0402 103.981,47.787 r90 top
R985 "10M" R0201 103.321,52.512 r90 top
RP800 "33R" RES_MNR04-8 58.082,37.678 r90 top
RP801 "33R" RES_MNR04-8 66.568,43.942 r90 top
ST701 "2X1 2.54MM" HDR_M254-1X2 2.875,2.08 r90 top locked
SW1 "PTS810" SW_CK_PTS810_SJM_250 99,37.7 r90 top
SW100 "PTS810" SW_CK_PTS810_SJM_250 52.5,13 r0 top
SW101 "PTS810" SW_CK_PTS810_SJM_250 40.5,13 r0 top
SW704 "DPDT_SW_SMD" CK_DPDT_JS202011SCQN 20.9,4.5 r180 top locked
TAB1 "Comment" TAB_V-CUT_L7.0_W2.4 12,0 r180 top
TAB2 "Comment" TAB_V-CUT_L7.0_W2.4 60,0 r180 top
TAB3 "Comment" TAB_V-CUT_L7.0_W2.4 98,0 r180 top
TAB4 "Comment" TAB_V-CUT_L7.0_W2.4 12,60 r0 top
TAB5 "Comment" TAB_V-CUT_L7.0_W2.4 60,60 r0 top
TAB6 "Comment" TAB_V-CUT_L7.0_W2.4 98,60 r0 top
TP156 "TP_SMD" TP_1.0_SMD 15.3,4.6 r180 bottom
TP400 "TP_SMD" TP_1.0_SMD 82.175,28.4 r180 bottom
TP700 "TP_SMD" TP_1.0_SMD 37.85,29.45 r90 bottom
TP701 "TP_SMD" TP_1.0_SMD 34.475,32.5 r90 bottom
TP703 "TP_SMD" TP_1.0_SMD 28.9,4.7 r180 bottom
TP705 "TP_SMD" TP_1.0_SMD 41.75,33.775 r180 bottom
TP706 "TP_SMD" TP_1.0_SMD 32.8,44.5 r90 bottom
TP707 "TP_SMD" TP_1.0_SMD 40.3,44.1 r90 bottom
TP708 "TP_SMD" TP_1.0_SMD 48.875,31.575 r90 bottom
TP709 "TP_SMD" TP_1.0_SMD 23.425,2.725 r90 bottom
TP711 "TP_SMD" TP_1.0_SMD 40.375,32.075 r90 bottom
TP712 "TP_SMD" TP_1.0_SMD 39.7,34.4 r90 bottom
TP713 "TP_SMD" TP_1.0_SMD 44.255,34.025 r90 bottom
TP714 "TP_SMD" TP_1.0_SMD 43.025,31.875 r90 bottom
TP715 "TP_SMD" TP_1.0_SMD 32.025,31.05 r180 bottom
TP923 "TP_SMD" TP_1.0_SMD 46.4,31.8 r90 bottom
TP930 "TP_SMD" TP_1.0_SMD 65.25,29.3 r180 bottom
TPH100 "PROTO_TH" PROTO_TH 99,29 r0 top
TPH101 "PROTO_TH" PROTO_TH 99,32 r0 top
TPJ600 "TP_SMD" TP_1.0_SMD 14.353,32.302 r90 bottom locked
TPJ606 "TP_SMD" TP_1.0_SMD 97.404,47.202 r90 bottom locked
TPJ607 "TP_SMD" TP_1.0_SMD 66.653,44.101 r90 bottom locked
TPJ608 "TP_SMD" TP_1.0_SMD 34.528,20.527 r90 bottom locked
TPJ611 "TP_SMD" TP_1.0_SMD 10.15,51.3 r180 bottom locked
TPJ612 "TP_SMD" TP_1.0_SMD 10.15,53.85 r180 bottom locked
TPJ613 "TP_SMD" TP_1.0_SMD 12.7,53.85 r180 bottom locked
TPJ614 "TP_SMD" TP_1.0_SMD 7.55,49.8 r180 bottom locked
TPJ650 "TP_SMD" TP_1.0_SMD 108.25,43.248 r90 bottom locked
TPJ651 "TP_SMD" TP_1.0_SMD 108.25,39.7 r90 bottom locked
TPJ652 "TP_SMD" TP_1.0_SMD 61.303,16.102 r90 bottom locked
TPJ653 "TP_SMD" TP_1.0_SMD 51.953,16.102 r90 bottom locked
TPJ811 "TP_SMD" TP_1.0_SMD 77.9,52.7 r180 bottom locked
TPJ812 "TP_SMD" TP_1.0_SMD 81.65,53.45 r180 bottom locked
TPJ814 "TP_SMD" TP_1.0_SMD 84.35,54.3 r180 bottom locked
TPJ817 "TP_SMD" TP_1.0_SMD 102.65,48.35 r180 bottom locked
TPJ818 "TP_SMD" TP_1.0_SMD 71.55,40.95 r180 bottom locked
TPJ820 "TP_SMD" TP_1.0_SMD 80.2,50.95 r180 bottom locked
TPJ900 "TP_SMD" TP_1.0_SMD 41.602,37.9 r90 bottom locked
TPJ901 "TP_SMD" TP_1.0_SMD 44.053,38.55 r90 bottom locked
TPJ902 "TP_SMD" TP_1.0_SMD 24.6,41.4 r180 bottom locked
TPJ905 "TP_SMD" TP_1.0_SMD 54.678,41.126 r90 bottom
TPJ908 "TP_SMD" TP_1.0_SMD 43.952,45.601 r90 bottom locked
TPJ909 "TP_SMD" TP_1.0_SMD 42.651,43.427 r90 bottom locked
TPJ910 "TP_SMD" TP_1.0_SMD 48.003,29.65 r90 bottom locked
TPJ911 "TP_SMD" TP_1.0_SMD 45.453,28.85 r90 bottom locked
TPJ912 "TP_SMD" TP_1.0_SMD 50.751,34.225 r90 bottom locked
TPJ913 "TP_SMD" TP_1.0_SMD 50.751,30.501 r90 bottom locked
TPJ950 "TP_SMD" TP_1.0_SMD 24.452,17.1 r90 bottom locked
TPJ953 "TP_SMD" TP_1.0_SMD 42.001,25.251 r90 bottom locked
TPJ954 "TP_SMD" TP_1.0_SMD 43.253,27.501 r90 bottom locked
TPJ955 "TP_SMD" TP_1.0_SMD 44.503,25.251 r90 bottom locked
TPJ956 "TP_SMD" TP_1.0_SMD 52.753,39.251 r90 bottom locked
TPJ957 "TP_SMD" TP_1.0_SMD 51.799,27.599 r180 bottom locked
TPJ958 "TP_SMD" TP_1.0_SMD 53.15,25.45 r180 bottom locked
TPJ959 "TP_SMD" TP_1.0_SMD 54.499,27.599 r90 bottom locked
TPJ960 "TP_SMD" TP_1.0_SMD 53.899,32.598 r90 bottom locked
TPJ961 "TP_SMD" TP_1.0_SMD 53.95,30.05 r180 bottom locked
U1 "EFM32PG28B310F1024IM68-A" QFN40P800X800X90_HS-69N 85.6,32.8 r0 top
U102 "Si7021-A20" DFN6_M100_3.0X3.0_EP_SI7021 111.45,50.05 r90 top
U103 "TS3A4751" QFN14_M040_2.0X2.0_TI_RUC 104.388,50.251 r90 top
U600 "LP3982ILD-ADJ" LLP8_MA65_W3.0 14.7,55.763 r0 top
U603 "TLV70536" DSBGA4_M040_0.8X0.8_TI_YFP 39.15,29.4 r180 top
U606 "MCP6001T" SOT65P210X110-5N 42.861,26.292 r270 top
U622 "MCP6001T" SOT65P210X110-5N 59.5,30.521 r180 top
U700 "SIP32431" TDFN4_M050_1.6X1.2_EP_VISH 30.258,32.384 r0 top
U701 "LP3982ILD-ADJ" LLP8_MA65_W3.0 31.728,25.592 r180 top
U702 "TS3A4751" QFN14_M040_2.0X2.0_TI_RUC 29.111,30.119 r180 top
U703 "LTC6102CDD" DFN8_M050_3.0X3.0_EP_LT_DD 36.329,36.808 r180 top
U704 "AD8656" MSOP8_M065_W3.0 36.45,41 r0 top
U800 "74LVC4066" TSOP65P640X110-14L_A1 72.1,44.5 r0 top
U802 "74LVC4066" TSOP65P640X110-14L_A1 72.1,38.5 r0 top
U803 "SN74LVC2G125DCUR" TSSOP50P310X90-8L 59.071,34.849 r0 top
U804 "SN74LVC2G125DCUR" TSSOP50P310X90-8L 50.503,35.704 r180 top
U805 "TS3A4751" QFN14_M040_2.0X2.0_TI_RUC 63.4,37 r90 top
U806 "74LVC4066" TSOP65P640X110-14L_A1 72.1,32 r0 top
U808 "74LVC8T245" TSOP65P640X120-24L 61.7,43.2 r0 top
U809 "SN74LVC2G125DCUR" TSSOP50P310X90-8L 54.948,37.735 r180 top
U810 "74LVC4066" DHVQFN14_M050_2.5X3_EP_NXP 68.135,27.393 r270 top
U812 "TS3A4751" QFN14_M040_2.0X2.0_TI_RUC 63.4,29.5 r90 top
U860 "74LVC1T45" SON35P100X35-6L 54,45 r90 top
U861 "74LVC1T45" SON35P100X35-6L 67.223,40.343 r90 top
U862 "74LVC1T45" SON35P100X35-6L 60.523,38.135 r90 top
U863 "74LVC1T45" SON35P100X35-6L 66.586,33.913 r90 top
U900 "EFM32GG12B410F1024GL120-A" BGA120_M050_7.0X7.0_EFM32GGR 48.5,41.5 r180 top
U901 "M24C02" DFN50P300X60_HS-9N 54.2,47.2 r0 top
U902 "MX25R8035F" SOP127P600X175-8L 51.097,31.589 r0 top
U910 "ADC084S021" VSSOP10_M050_W3.0_TI_DGS 43.574,31.72 r0 top
U950 "TS3A4751" QFN14_M040_2.0X2.0_TI_RUC 55.125,41.9 r270 top
X1 "39 MHz" XTAL200X160X50 82,27 r0 top
X2 "32.768 kHz" XTAL160X100X50 79.751,34.6 r90 top
X900 "48 MHz" XTAL200X160X50 47.75,46.75 r0 top
? "Comment" LOGO_GECKO_H6.0 95,41.35 r0 top

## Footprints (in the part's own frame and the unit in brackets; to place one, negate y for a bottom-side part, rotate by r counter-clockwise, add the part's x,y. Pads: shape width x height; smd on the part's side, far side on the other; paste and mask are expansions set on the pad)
BAT_HOLD_MPD_BK-912_CR2032 [mil] "MPD Battery Holder BK-912 (for CR2032)"
  rrect20% 110x200 smd: 1(-430,0) 1(430,0)
  round 157.48 smd paste-295.67 mask-82.68: 2(0,0)
  body extent -450,-394 450,393, height 171
BGA120_M050_7.0X7.0_EFM32GGR [mm] "BGA, 120 Leads, Body 7.0x7.0mmx1,30mm, Pitch 0.50mm (191111)"
  round 0.2 smd mask+0.04: A1(-3,3) A2(-2.5,3) A3(-2,3) A4(-1.5,3) A5(-1,3) A6(-0.5,3) A7(0,3) A8(0.5,3) A9(1,3) A10(1.5,3) A11(2,3) A12(2.5,3) A13(3,3) B1(-3,2.5) B2(-2.5,2.5) B3(-2,2.5) B4(-1.5,2.5) B5(-1,2.5) B6(-0.5,2.5) B7(0,2.5) B8(0.5,2.5) B9(1,2.5) B10(1.5,2.5) B11(2,2.5) B12(2.5,2.5) B13(3,2.5) C1(-3,2) C2(-2.5,2) C3(-2,2) C4(-1.5,2) C5(-1,2) C6(-0.5,2) C7(0,2) C8(0.5,2) C9(1,2) C10(1.5,2) C11(2,2) C12(2.5,2) C13(3,2) D1(-3,1.5) D2(-2.5,1.5) D3(-2,1.5) D11(2,1.5) D12(2.5,1.5) D13(3,1.5) E1(-3,1) E2(-2.5,1) E3(-2,1) E11(2,1) E12(2.5,1) E13(3,1) F1(-3,0.5) F2(-2.5,0.5) F3(-2,0.5) F11(2,0.5) F12(2.5,0.5) F13(3,0.5) G1(-3,0) G2(-2.5,0) G3(-2,0) G11(2,0) G12(2.5,0) G13(3,0) H1(-3,-0.5) H2(-2.5,-0.5) H3(-2,-0.5) H11(2,-0.5) H12(2.5,-0.5) H13(3,-0.5) J1(-3,-1) J2(-2.5,-1) J3(-2,-1) J11(2,-1) J12(2.5,-1) J13(3,-1) K1(-3,-1.5) K2(-2.5,-1.5) K3(-2,-1.5) K11(2,-1.5) K12(2.5,-1.5) K13(3,-1.5) L1(-3,-2) L2(-2.5,-2) L3(-2,-2) L4(-1.5,-2) L5(-1,-2) L6(-0.5,-2) L7(0,-2) L8(0.5,-2) L9(1,-2) L10(1.5,-2) L11(2,-2) L12(2.5,-2) L13(3,-2) M1(-3,-2.5) M2(-2.5,-2.5) M3(-2,-2.5) M4(-1.5,-2.5) M5(-1,-2.5) M6(-0.5,-2.5) M7(0,-2.5) M8(0.5,-2.5) M9(1,-2.5) M10(1.5,-2.5) M11(2,-2.5) M12(2.5,-2.5) M13(3,-2.5) N1(-3,-3) N2(-2.5,-3) N3(-2,-3) N4(-1.5,-3) N5(-1,-3) N6(-0.5,-3) N7(0,-3) N8(0.5,-3) N9(1,-3) N10(1.5,-3) N11(2,-3) N12(2.5,-3) N13(3,-3)
  body extent -3.5,-3.5 3.5,3.5, height 1.3
C0201#1 [mm] "Capacitor, 9291, HiDens (170502)"
  rrect25% 0.36x0.32 smd paste-0.015: 1(-0.275,0) 2(0.275,0)
  Top Layer pour cut-out: -0.075,-0.2 -0.075,0.2 0.075,0.2 0.075,-0.2
  body extent -0.32,-0.13 0.32,0.13, height 0.3
C0201#2 [mm] "Capacitor, 9291, HiDens (170502)"
  rrect25% 0.36x0.32 smd paste-0.015 mask+0.05: 1(-0.275,0) 2(0.275,0)
  Top Layer pour cut-out: -0.075,-0.2 -0.075,0.2 0.075,0.2 0.075,-0.2
  body extent -0.32,-0.13 0.32,0.13, height 0.3
C0402 [mm] "Chip Capacitor, 2-Leads, Body 1.0x0.5mm, IPC High Density (190308)"
  rrect20% 0.5x0.5 smd mask+0.051: 1(-0.5,0) 2(0.5,0)
  Top Layer pour cut-out: -0.225,-0.3 -0.225,0.3 0.225,0.3 0.225,-0.3
  body extent -0.5,-0.25 0.5,0.25, height 0.6
C0603 [mm] "Capacitor, 0603, HiDens (190130)"
  rrect25% 0.8x0.85 smd: 1(-0.7,0) 2(0.7,0)
  Top Layer pour cut-out: -0.275,-0.55 -0.275,0.55 0.275,0.55 0.275,-0.55
  body extent -0.88,-0.48 0.87,0.48, height 0.95
CK_DPDT_JS202011SCQN [mm] "Switch, C & K DPDT JS202011SCQN (190314)"
  rrect50% 1.2x2.5 smd: 1(-2.5,-2.75) 2(0,-2.75) 3(2.5,-2.75) 4(-2.5,2.75) 5(0,2.75) 6(2.5,2.75)
  body extent -4.5,-3.5 4.5,3.5, height 5.65
COIL_0402 [mm] "COIL_0402_L (3D from Wurth) (190308)"
  rrect20% 0.55x0.5 smd mask+0.051: 1(-0.525,0) 2(0.525,0)
  Top Layer pour cut-out: -0.225,-0.3 -0.225,0.3 0.225,0.3 0.225,-0.3
  body extent -0.5,-0.25 0.5,0.25, height 0.5
COIL_0603_L [mm] "COIL 0603_L (= L0603_0.8_L)"
  rrect10% 0.75x0.88 smd: 1(-0.725,0) 2(0.725,0)
  Top Layer pour cut-out: -0.275,-0.55 -0.275,0.55 0.275,0.55 0.275,-0.55
  body extent -0.8,-0.4 0.8,0.4, height 0.8
COIL_1008 [mm] "Coil, HiDens (C) (190312)"
  rrect15% 0.93x2.12 smd: 1(-1.035,0) 2(1.035,0)
  body extent -1.35,-1.1 1.35,1.1, height 1
COIL_BOURNS_SDR0604 [mm] "Coil Bourns SDR0604 (210208)"
  rrect20% 1x1 smd paste-100: 1(-2,0) 2(2,0)
  Top Layer region: -3,-2.101 -3,2.1 -3,2.179 -2.969,2.333 -2.909,2.479 -2.822,2.61 -2.71,2.722 -2.579,2.809 -2.433,2.869 -2.279,2.9 -2.2,2.9 -2.2,2.9 -1,2.9 -0.98,2.9 -0.943,2.885 -0.915,2.857 -0.9,2.82 -0.9,2.8 -0.9,2.8 -0.9,-2.8 -0.9,-2.82 -0.915,-2.857 -0.943,-2.885 -0.98,-2.9 -1,-2.9 -1,-2.9 -2.2,-2.9 -2.279,-2.9 -2.433,-2.869 -2.578,-2.809 -2.709,-2.722 -2.821,-2.61 -2.909,-2.48 -2.969,-2.334 -3,-2.18 -3,-2.101
  Top Layer region: 3,2.101 3,-2.1 3,-2.179 2.969,-2.333 2.909,-2.479 2.822,-2.61 2.71,-2.722 2.579,-2.809 2.433,-2.869 2.279,-2.9 2.2,-2.9 2.2,-2.9 1,-2.9 0.98,-2.9 0.943,-2.885 0.915,-2.857 0.9,-2.82 0.9,-2.8 0.9,-2.8 0.9,2.8 0.9,2.82 0.915,2.857 0.943,2.885 0.98,2.9 1,2.9 1,2.9 2.2,2.9 2.279,2.9 2.433,2.869 2.578,2.809 2.709,2.722 2.821,2.61 2.909,2.48 2.969,2.334 3,2.18 3,2.101
  body extent -2.9,-2.9 2.9,2.9, height 4.81
DFN6_M100_3.0X3.0_EP_SI7021 [mm] "(191031)"
  rrect20% 0.85x0.45 smd: 1(-1.45,1) 2(-1.45,0) 3(-1.45,-1) 4(1.45,-1) 5(1.45,0) 6(1.45,1)
  rrect20% 1.6x2.5 smd: 7(0,0)
  body extent -1.5,-1.5 1.5,1.5, height 1.22
DFN8_M050_3.0X3.0_EP_LT_DD [mm] "DFN 8 Lead, Pitch 0.5, 3.0x3.0x0.75 Exposed Pad, Linear Tech (171004)"
  rrect50% 0.7x0.25 smd paste-0.025 mask+0.07: 1(-1.4,0.75) 2(-1.4,0.25) 3(-1.4,-0.25) 4(-1.4,-0.75) 5(1.4,-0.75) 6(1.4,-0.25) 7(1.4,0.25) 8(1.4,0.75)
  rect 1x1.8 smd paste-1 mask+0: 9(0,0)
  Top Layer region: 0.825,1.2 -0.693,1.2 -0.825,1.095 -0.825,-1.2 0.825,-1.2
  body extent -1.56,-1.55 1.56,1.55, height 0.8
DFN50P300X60_HS-9N [mm] "UFDFPN8, 8-Leads, Body 2.00x3.00mm, Pitch 0.50mm, DFN8"
  rect 0.6x0.3 smd: 1(-1.4,0.75) 2(-1.4,0.25) 3(-1.4,-0.25) 4(-1.4,-0.75) 5(1.4,-0.75) 6(1.4,-0.25) 7(1.4,0.25) 8(1.4,0.75)
  rect 1.6x1.6 smd: 9(0,0)
  body extent -1.5,-1 1.5,1, height 0.6
DFN2111-7_M050_1.2X2.1_NXP [mm] "DFN2111-7 NXP Pitch 035 1.2x2.1x0.5, NXP (190312)"
  rrect20% 0.53x0.19 smd mask+0.05: 1(-0.415,0.75) 2(-0.415,0.25) 3(-0.415,-0.25) 4(-0.415,-0.75) 5(0.415,-0.5) 6(0.415,0) 7(0.415,0.5)
  body extent -0.6,-1.05 0.6,1.05, height 0.51
DHVQFN14_M050_2.5X3_EP_NXP [mm] "DHVQFN, 14 Leads, 2.5x3.0x0.85, Pitch 0.50, Thermal Pad 1.0x1.5 (190314)"
  oval 0.3x0.7 smd: 1(-0.25,1.45) 7(-0.25,-1.45) 8(0.25,-1.45) 14(0.25,1.45)
  oval 0.7x0.3 smd: 2(-1.2,1) 3(-1.2,0.5) 4(-1.2,0) 5(-1.2,-0.5) 6(-1.2,-1) 9(1.2,-1) 10(1.2,-0.5) 11(1.2,0) 12(1.2,0.5) 13(1.2,1)
  rrect10% 1x1.5 smd: 17(0,0)
  body extent -1.25,-1.5 1.25,1.5, height 1.1
DIOC1005X04N [mm] "Chip Diode, 2-Leads, Body 1.00x0.50mm, IPC Medium Density"
  rect 0.6x0.7 smd: 1(-0.475,0) 2(0.475,0)
  body extent -0.5,-0.25 0.5,0.25, height 0.32
DSBGA4_M040_0.8X0.8_TI_YFP [mm] "DS-BGA, 4 Leads, Body 0.8x0.8 H:0.5, Pitch 0.40"
  round 0.23 smd mask+0.04: A1(-0.2,0.2) A2(0.2,0.2) B1(-0.2,-0.2) B2(0.2,-0.2)
  body extent -0.4,-0.4 0.4,0.4, height 0.51
FCI_10137065_USB-C_RCPT [mm] "FCI AMPHENOL 10137065 USB-C Receptacle (Slot PinInPaste) (180404)"
  oval 1.3x2.6 hole 0.7 slot 2 at 90 deg: 25(-4.32,-3.05) 26(4.32,-3.05)
  oval 1.3x2.6 on Top Paste: 25(-4.32,-3.05) 26(4.32,-3.05)
  oval 1.2x2.489 on Top Paste: 27(-4.32,2)
  oval 1.2x2.5 hole 0.6 slot 1.9 at 90 deg paste+0: 27(-4.32,2)
  oval 1.638x1.194 on Top Paste: 27(-4.025,1.35)
  oval 1.647x1.2 hole 0.6 slot 1.247 at 0 deg: 27(-4.025,1.35)
  oval 1.847x1.2 hole 0.6 slot 1.247 at 0 deg: 28(4.025,1.35)
  oval 1.841x1.194 on Top Paste: 28(4.025,1.35)
  oval 1.2x2.5 hole 0.6 slot 1.9 at 90 deg: 28(4.32,2)
  oval 1.194x2.489 on Top Paste: 28(4.32,2)
  rrect20% 0.27x0.9 smd mask+0.076: A1(-2.625,2.7) A2(-2.125,2.7) A3(-1.625,2.7) A4(-1.125,2.7) A5(-0.625,2.7) A6(-0.125,2.7) A7(0.375,2.7) A8(0.875,2.7) A9(1.375,2.7) A10(1.875,2.7) A11(2.375,2.7) A12(2.875,2.7)
  rrect20% 0.27x0.8 smd mask+0.076: B1(2.625,1.1) B2(2.125,1.1) B3(1.625,1.1) B4(1.125,1.1) B5(0.625,1.1) B6(0.125,1.1) B7(-0.375,1.1) B8(-0.875,1.1) B9(-1.375,1.1) B10(-1.875,1.1) B11(-2.375,1.1) B12(-2.875,1.1)
  round 0 hole 0.6 unplated mask+0.102: M1(-3.6,0)
  round 0 hole 0.5 slot 0.85 at 0 deg unplated mask+0.102: M2(3.6,0)
  Top Layer keep-out region: -3.9,-4.85 3.9,-4.85 3.9,0.4 -3.9,0.4
  body extent -4.47,-5.3 4.47,2.85, height 3.14
HDR_M254-1X2 [mm] "Connector; Header; 2 Position (170508)"
  round 1.6 hole 1: 1(0,0) 2(2.54,0)
  body extent -1.07,-1.17 3.61,1.17, height 8.12
HDR_M254-1X16_NO_3D [mm] "No 3D model for this component (200325)"
  round 1.5 hole 0.9: 1(0,0) 2(2.54,0) 3(5.08,0) 4(7.62,0) 5(10.16,0) 6(12.7,0) 7(15.24,0) 8(17.78,0) 9(20.32,0) 10(22.86,0) 11(25.4,0) 12(27.94,0) 13(30.48,0) 14(33.02,0) 15(35.56,0) 16(38.1,0)
HDR_SULLINS_M127_PEG-2X10 [mil] "Sullins, GRPB102VQS (180319)"
  rrect50% 30x87 smd: 1(-25,-72.5) 2(-25,72.5) 3(25,-72.5) 4(25,72.5) 5(75,-72.5) 6(75,72.5) 7(125,-72.5) 8(125,72.5) 9(175,-72.5) 10(175,72.5) 11(225,-72.5) 12(225,72.5) 13(275,-72.5) 14(275,72.5) 15(325,-72.5) 16(325,72.5) 17(375,-72.5) 18(375,72.5) 19(425,-72.5) 20(425,72.5)
  round 0 hole 39.37 unplated mask+3.94: M1(0,0) M2(400,0)
  body extent -50,-100 450,101, height 197
HOLE_3.0_5.0_PL [mm] "Hole 3.0 mm, Plated (171122)"
  round 5 hole 3: 1(0,0)
HOLE_3.0_NPL [mm] "HOLE_3.0_NPL (170815)"
  round 0 hole 3 unplated mask+0.2: 1(0,0)
  body extent -1.5,-1.5 1.5,1.5
LABEL_4CORNERS_19.0X6.0 [mm]
  silkscreen extent -9.5,-3 9.5,3
LABEL_P101_PIN_TABLE_SL [mm]
  silkscreen extent -2.4,-12.5 2.4,12.5
LCD_TRI-T_CL010-1087-03 [mm] "LCD_TRI-T_CL010-1087-03 (190320)"
  round 1.4 hole 0.8: 1(-13,-12.7) 2(-11,-12.7) 3(-9,-12.7) 4(-7,-12.7) 5(-5,-12.7) 6(-3,-12.7) 7(-1,-12.7) 8(1,-12.7) 9(3,-12.7) 10(5,-12.7) 11(7,-12.7) 12(9,-12.7) 13(11,-12.7) 14(13,-12.7) 15(13,12.7) 16(11,12.7) 17(9,12.7) 18(7,12.7) 19(5,12.7) 20(3,12.7) 21(1,12.7) 22(-1,12.7) 23(-3,12.7) 24(-5,12.7) 25(-7,12.7) 26(-9,12.7) 27(-11,12.7) 28(-13,12.7)
LED_0402_CAT2 [mm] "(200921)"
  rrect10% 0.45x0.6 smd: 1(-0.45,0) 2(0.45,0)
  body extent -0.55,-0.33 0.55,0.33, height 0.25
LED_AVAGO_HSMF-C165-4 [mm] "LED (dual) Avago HSMF-C165 Grn+Red 1.6x0.8x0.5 (200226)"
  rrect20% 0.7x0.4 smd: 1(-0.65,-0.35) 2(-0.65,0.35) 3(0.65,0.35) 4(0.65,-0.35)
  body extent -0.8,-0.4 0.8,0.4, height 0.52
LLP8_MA65_W3.0 [mm] "LLP8_MA65_W3.0 (180615)"
  rrect20% 0.5x0.25 smd: 1(-1.15,0.75) 2(-1.15,0.25) 3(-1.15,-0.25) 4(-1.15,-0.75) 5(1.15,-0.75) 6(1.15,-0.25) 7(1.15,0.25) 8(1.15,0.75)
  rrect20% 1.2x1.5 smd: 9(0,0)
  body extent -1.55,-1.3 1.55,1.3, height 0.8
LOGO_EFM32_W18.0 [mm]
  silkscreen extent 12.4,0.08 18.08,2.31
LOGO_GECKO_H6.0 [mm] "Silicon Labs, Gecko logo"
  silkscreen extent 0.03,0.04 5.31,6.01
LOGO_SEGGER_10.0X5.0_SM [mm] "Logo, Segger 10.0x5.0, Top Solder + M19 + Top Overlay"
LOGO_SILABS_W14.0_SILK [mm] "LOGO_SILABS_W14.0 SILKSCREEN ONLY"
  silkscreen extent 0.03,0 13.99,6.83
LOGO_SILABS_W18.0 [mm]
  silkscreen extent 0.02,0.02 16.98,8.32
MSOP8_M065_W3.0 [mm] "MSOP, 8-Leads, Body 3.0x3.0mm, Pitch 0.65mm (170921)"
  rrect20% 0.889x0.42 smd mask+0.048: 1(-2.105,0.975) 2(-2.105,0.325) 3(-2.105,-0.325) 4(-2.105,-0.975) 5(2.106,-0.975) 6(2.106,-0.325) 7(2.106,0.325) 8(2.106,0.975)
  body extent -1.55,-1.55 1.55,1.55, height 1.11
PROTO_TH [mil] "Test Point, 1.0 mm (= TP_1.0_D62)"
  round 62 hole 39.37: 1(0,0)
QFN14_M040_2.0X2.0_TI_RUC [mm] "QFN 14 Leads, Pitch 0.4 mm, 2.0 x 2.0 H: 0.37, TI: RUC (180613)"
  rrect20% 0.68x0.2 smd: 1(-0.885,0.8) 2(-0.885,0.4) 3(-0.885,0) 4(-0.885,-0.4) 5(-0.885,-0.8) 8(0.885,-0.8) 9(0.885,-0.4) 10(0.885,0) 11(0.885,0.4) 12(0.885,0.8)
  rrect20% 0.2x0.68 smd: 6(-0.2,-0.885) 7(0.2,-0.885) 13(0.2,0.885) 14(-0.2,0.885)
  body extent -1,-1 1,1, height 0.41
QFN40P800X800X90_HS-69N [mm] "QFN, 68-Leads, Body 8.00x8.00mm, Pitch 0.40mm, Thermal Pad 5.60x5.60mm, IPC Medium Density"
  oval 0.85x0.2 smd mask+0.08: 1(-3.95,3.2) 2(-3.95,2.8) 3(-3.95,2.4) 4(-3.95,2) 5(-3.95,1.6) 6(-3.95,1.2) 7(-3.95,0.8) 8(-3.95,0.4) 9(-3.95,0) 10(-3.95,-0.4) 11(-3.95,-0.8) 12(-3.95,-1.2) 13(-3.95,-1.6) 14(-3.95,-2) 15(-3.95,-2.4) 16(-3.95,-2.8) 17(-3.95,-3.2) 35(3.95,-3.2) 36(3.95,-2.8) 37(3.95,-2.4) 38(3.95,-2) 39(3.95,-1.6) 40(3.95,-1.2) 41(3.95,-0.8) 42(3.95,-0.4) 43(3.95,0) 44(3.95,0.4) 45(3.95,0.8) 46(3.95,1.2) 47(3.95,1.6) 48(3.95,2) 49(3.95,2.4) 50(3.95,2.8) 51(3.95,3.2)
  oval 0.2x0.85 smd mask+0.08: 18(-3.2,-3.95) 19(-2.8,-3.95) 20(-2.4,-3.95) 21(-2,-3.95) 22(-1.6,-3.95) 23(-1.2,-3.95) 24(-0.8,-3.95) 25(-0.4,-3.95) 26(0,-3.95) 27(0.4,-3.95) 28(0.8,-3.95) 29(1.2,-3.95) 30(1.6,-3.95) 31(2,-3.95) 32(2.4,-3.95) 33(2.8,-3.95) 34(3.2,-3.95) 52(3.2,3.95) 53(2.8,3.95) 54(2.4,3.95) 55(2,3.95) 56(1.6,3.95) 57(1.2,3.95) 58(0.8,3.95) 59(0.4,3.95) 60(0,3.95) 61(-0.4,3.95) 62(-0.8,3.95) 63(-1.2,3.95) 64(-1.6,3.95) 65(-2,3.95) 66(-2.4,3.95) 67(-2.8,3.95) 68(-3.2,3.95)
  rect 4x4 smd paste-5.8: 69(0,0)
  Top Layer region: -2.45,2.8 -2.8,2.45 -2.8,-2.8 2.8,-2.8 2.8,2.8
  body extent -4,-4 4,4, height 0.9
R0201 [mm] "Resistor (Chip2PinSM127P600-8N) (170921)"
  rrect25% 0.34x0.32 smd: 1(-0.3,0) 2(0.3,0)
  Top Layer pour cut-out: -0.1,-0.2 -0.1,0.2 0.1,0.2 0.1,-0.2
  body extent -0.32,-0.13 0.32,0.13, height 0.3
R0402 [mm] "Chip Resistor, 2-Leads, Body 1.0x0.5mm, HiDens (190308)"
  rrect20% 0.6x0.6 smd mask+0.051: 1(-0.45,0) 2(0.45,0)
  Top Layer pour cut-out: -0.125,-0.3 -0.125,0.3 0.125,0.3 0.125,-0.3
  body extent -0.5,-0.25 0.5,0.25, height 0.6
R0603 [mm] "Chip Resistor, 0603, HiDens (190130)"
  rrect25% 0.85x0.9 smd: 1(-0.7,0) 2(0.7,0)
  Top Layer pour cut-out: -0.25,-0.575 -0.25,0.575 0.25,0.575 0.25,-0.575
  body extent -0.88,-0.48 0.87,0.48, height 0.95
R1206 [mm] "Resistor, 1206, HiDens (191114)"
  rrect25% 0.85x1.65 smd paste-0.04 mask+0.07: 1(-1.425,0) 2(1.425,0)
  body extent -1.6,-0.8 1.6,0.8, height 1
RES_MNR04-8 [mm] "Resistor Array, ROHM MNR04 8-Pin 2.0x1.0x0.35 (!80615)"
  rrect20% 0.4x0.5 smd: 1(-0.75,-0.45) 4(0.75,-0.45) 5(0.75,0.45) 8(-0.75,0.45)
  rrect20% 0.3x0.5 smd: 2(-0.25,-0.45) 3(0.25,-0.45) 6(0.25,0.45) 7(-0.25,0.45)
  body extent -1,-0.4 1,0.4, height 0.5
SON35P100X35-6L [mm] "XSON6 SOT1202"
  rect 0.15x0.5 smd paste+0: 1(-0.35,-0.35) 2(0,-0.35) 3(0.35,-0.35) 4(0.35,0.35) 5(0,0.35) 6(-0.35,0.35)
  body extent -0.5,-0.5 0.5,0.5, height 0.35
SOP127P600X175-8L [mm] "SOP, 8-Leads, Body 4.90x3.90mm, Pitch 1.27mm, IPC High Density"
  rect 1.25x0.6 smd: 1(-2.625,1.905) 2(-2.625,0.635) 3(-2.625,-0.635) 4(-2.625,-1.905) 5(2.625,-1.905) 6(2.625,-0.635) 7(2.625,0.635) 8(2.625,1.905)
  body extent -1.95,-2.45 1.95,2.45, height 1.75
SOT23 [mm] "SOT23, 3-Leads, Body 2.95x2.80mm, Pitch 0.95mm, HiDens (171129)"
  rrect50% 0.9x0.6 smd: 1(-1.2,0.95) 2(-1.2,-0.95) 3(1.2,0)
  body extent -1.32,-1.5 1.32,1.5, height 1.08
SOT65P210X110-5N [mm] "SOT23, 5-Leads, Body 2.00x2.10mm, Pitch 0.65mm, IPC Medium Density"
  rect 0.95x0.45 smd: 1(-1.1,0.65) 2(-1.1,0) 3(-1.1,-0.65) 4(1.1,-0.65) 5(1.1,0.65)
  body extent -1.19,-1.13 1.19,1.13, height 1.09
SOT563_DIODES [mm] "SOT563 (_M050_W1.2_), 6-Leads, Body 1.60x1.20, Pitch 0.5, HiDens (170926)"
  rrect25% 0.5x0.375 smd: 1(-0.85,0.5) 2(-0.85,0) 3(-0.85,-0.5) 4(0.85,-0.5) 5(0.85,0) 6(0.85,0.5)
  body extent -0.66,-0.85 0.65,0.85, height 0.6
SW_CK_PTS810_SJM_250 [mm] "Switch C&K PTS810_SJM_250 (grey button) (180319)"
  rrect20% 1.05x0.65 smd: 1(-2.075,1.075) 2(2.075,1.075) 3(-2.075,-1.075) 4(2.075,-1.075)
  body extent -2.29,-1.6 2.29,1.6, height 2.5
TAB_V-CUT_L7.0_W2.4 [mm] "TAB V_CUT, Length 7.0, Width 2.4"
TDFN4_M050_1.6X1.2_EP_VISH [mm] "TDFN, 4-Leads, Body 1.60x1.20mm, IPC HiDens (180111)"
  rrect10% 0.55x0.3 smd: 1(-0.725,0.25) 2(-0.725,-0.25) 3(0.725,-0.25) 4(0.725,0.25)
  rrect10% 0.5x0.86 smd paste-0.05: 5(0,0)
  body extent -0.8,-0.6 0.8,0.6, height 0.61
TP_1.0_SMD [mm] "Test Point, 1.0 mm, SMD (170509)"
  round 1 smd paste-0.501: 1(0,0)
  body extent -0.5,-0.5 0.5,0.5, height 0.04
TSOP65P640X110-14L_A1 [mm] "TSOP, 14-Leads, Body 5.00x4.40mm, Pitch 0.65 and 0.75mm, IPC High Density"
  rect 1.35x0.6 smd: 1(-2.925,2.05) 7(-2.925,-2.05) 8(2.925,-2.05) 14(2.925,2.05)
  rect 1.35x0.4 smd: 2(-2.925,1.3) 3(-2.925,0.65) 4(-2.925,0) 5(-2.925,-0.65) 6(-2.925,-1.3) 9(2.925,-1.3) 10(2.925,-0.65) 11(2.925,0) 12(2.925,0.65) 13(2.925,1.3)
  body extent -3.3,-2.55 3.3,2.55, height 1.1
TSOP65P640X120-24L [mm] "TSSOP 24-Leads, Body 7.80x4.40mm, Pitch 0.65mm, IPC High Density"
  rrect25% 1.5x0.45 smd mask+0.051: 1(-2.9,3.575) 2(-2.9,2.925) 3(-2.9,2.275) 4(-2.9,1.625) 5(-2.9,0.975) 6(-2.9,0.325) 7(-2.9,-0.325) 8(-2.9,-0.975) 9(-2.9,-1.625) 10(-2.9,-2.275) 11(-2.9,-2.925) 12(-2.9,-3.575) 13(2.9,-3.575) 14(2.9,-2.925) 15(2.9,-2.275) 16(2.9,-1.625) 17(2.9,-0.975) 18(2.9,-0.325) 19(2.9,0.325) 20(2.9,0.975) 21(2.9,1.625) 22(2.9,2.275) 23(2.9,2.925) 24(2.9,3.575)
  body extent -3.28,-3.95 3.28,3.95, height 1.2
TSSOP50P310X90-8L [mm] "VSSOP, 8-Leads, Body 2.00x2.30mm, Pitch 0.50mm, IPC High Density"
  rect 0.75x0.25 smd: 1(-1.55,0.75) 2(-1.55,0.25) 3(-1.55,-0.25) 4(-1.55,-0.75) 5(1.55,-0.75) 6(1.55,-0.25) 7(1.55,0.25) 8(1.55,0.75)
  body extent -1.55,-1 1.55,1, height 0.77
VSSOP10_M050_W3.0_TI_DGS [mm] "VSSOP, 10-Leads, 3.0x3.0x(max1.1), Pitch 0.50mm, (TI: DGS) (190816)"
  rrect20% 1.45x0.3 smd: 1(-2.2,1) 2(-2.2,0.5) 3(-2.2,0) 4(-2.2,-0.5) 5(-2.2,-1) 6(2.2,-1) 7(2.2,-0.5) 8(2.2,0) 9(2.2,0.5) 10(2.2,1)
  body extent -1.5,-1.5 1.5,1.5, height 1.1
WCON_1125B-1210_HOR_PEG-2X10 [mm] "WCON 2x10 header (201021)"
  rrect50% 1.27x3.175 smd: 1(-1.27,4.24) 2(-1.27,8.43) 3(1.27,4.24) 4(1.27,8.43) 5(3.81,4.24) 6(3.81,8.43) 7(6.35,4.24) 8(6.35,8.43) 9(8.89,4.24) 10(8.89,8.43) 11(11.43,4.24) 12(11.43,8.43) 13(13.97,4.24) 14(13.97,8.43) 15(16.51,4.24) 16(16.51,8.43) 17(19.05,4.24) 18(19.05,8.43) 19(21.59,4.24) 20(21.59,8.43)
  round 0 hole 1.9 unplated paste+0.91 mask+0.1: M1(0,0) M2(20.32,0)
  body extent -2.54,-7.11 22.86,9.15, height 6.1
WCON_3132_HDR_M127_SMD-2X10 [mm] "WCON_3132_HDR_M127_SMD-2X10 (210215)"
  rrect50% 0.74x2.4 smd: 1(-5.715,-1.95) 2(-5.715,1.95) 3(-4.445,-1.95) 4(-4.445,1.95) 5(-3.175,-1.95) 6(-3.175,1.95) 7(-1.905,-1.95) 8(-1.905,1.95) 9(-0.635,-1.95) 10(-0.635,1.95) 11(0.635,-1.95) 12(0.635,1.95) 13(1.905,-1.95) 14(1.905,1.95) 15(3.175,-1.95) 16(3.175,1.95) 17(4.445,-1.95) 18(4.445,1.95) 19(5.715,-1.95) 20(5.715,1.95)
  body extent -6.35,-4.53 6.35,2.84, height 6.58
WELLSHOW_C02AN31_SMA_TH [mm] "Wellshow C02AN31P00101 SMA (210208)"
  round 2.54 hole 1.5: 1(0,0) 2(-2.54,-2.54) 3(2.54,-2.54) 4(2.54,2.54) 5(-2.54,2.54)
  body extent -3.2,-3.2 3.2,3.2, height 9.5
X2-DFN1006-2 [mm] "Diodes case X2-DFN1006-2 part DESD5V0S1BLD (201012)"
  rrect20% 0.4x0.7 smd mask+0.04: 1(-0.35,0) 2(0.35,0)
  body extent -0.5,-0.3 0.5,0.3, height 0.41
X2-DFN2015-3_DIODES [mm] "X2-DFN2015-3 DIODES (181204)"
  rrect10% 0.5x0.31 smd mask+0.07: 1(-0.9,0.5) 2(-0.9,-0.5)
  rrect10% 0.75x0.31 smd mask+0.07: 3(0.775,0)
  Top Layer region: 0.5,0.55 0.5,-0.55 0.5,-0.57 0.485,-0.607 0.457,-0.635 0.42,-0.65 0.4,-0.65 0.4,-0.65 -0.4,-0.65 -0.42,-0.65 -0.457,-0.635 -0.485,-0.607 -0.5,-0.57 -0.5,-0.55 -0.5,-0.55 -0.5,0.55 -0.5,0.57 -0.485,0.607 -0.457,0.635 -0.42,0.65 -0.4,0.65 -0.4,0.65 0.4,0.65 0.42,0.65 0.457,0.635 0.485,0.607 0.5,0.57 0.5,0.55
  body extent -1.04,-0.79 1.04,0.79, height 0.4
XTAL160X100X50 [mm] "KDS Crystal, 2 Leads, 1.6mm X 1mm. Height 0.5mm, DST1610A"
  rrect25% 0.7x1.2 smd: 1(-0.55,0) 2(0.55,0)
  body extent -0.8,-0.5 0.8,0.5, height 0.5
XTAL200X160X50 [mm] "TAISAW Crystal, 4 Leads,  2.0mm X 1.6mm. Height 0.5mm"
  rrect20% 0.95x0.85 smd: 1(-0.725,-0.575) 2(0.725,-0.575) 3(0.725,0.575) 4(-0.725,0.575)
  body extent -1,-0.8 1,0.8, height 0.5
